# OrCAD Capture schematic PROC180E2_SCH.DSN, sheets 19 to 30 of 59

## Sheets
19 52. CURRENT MONITORING - 2: size C; title: CURRENT MONITORING DEVICES - 2
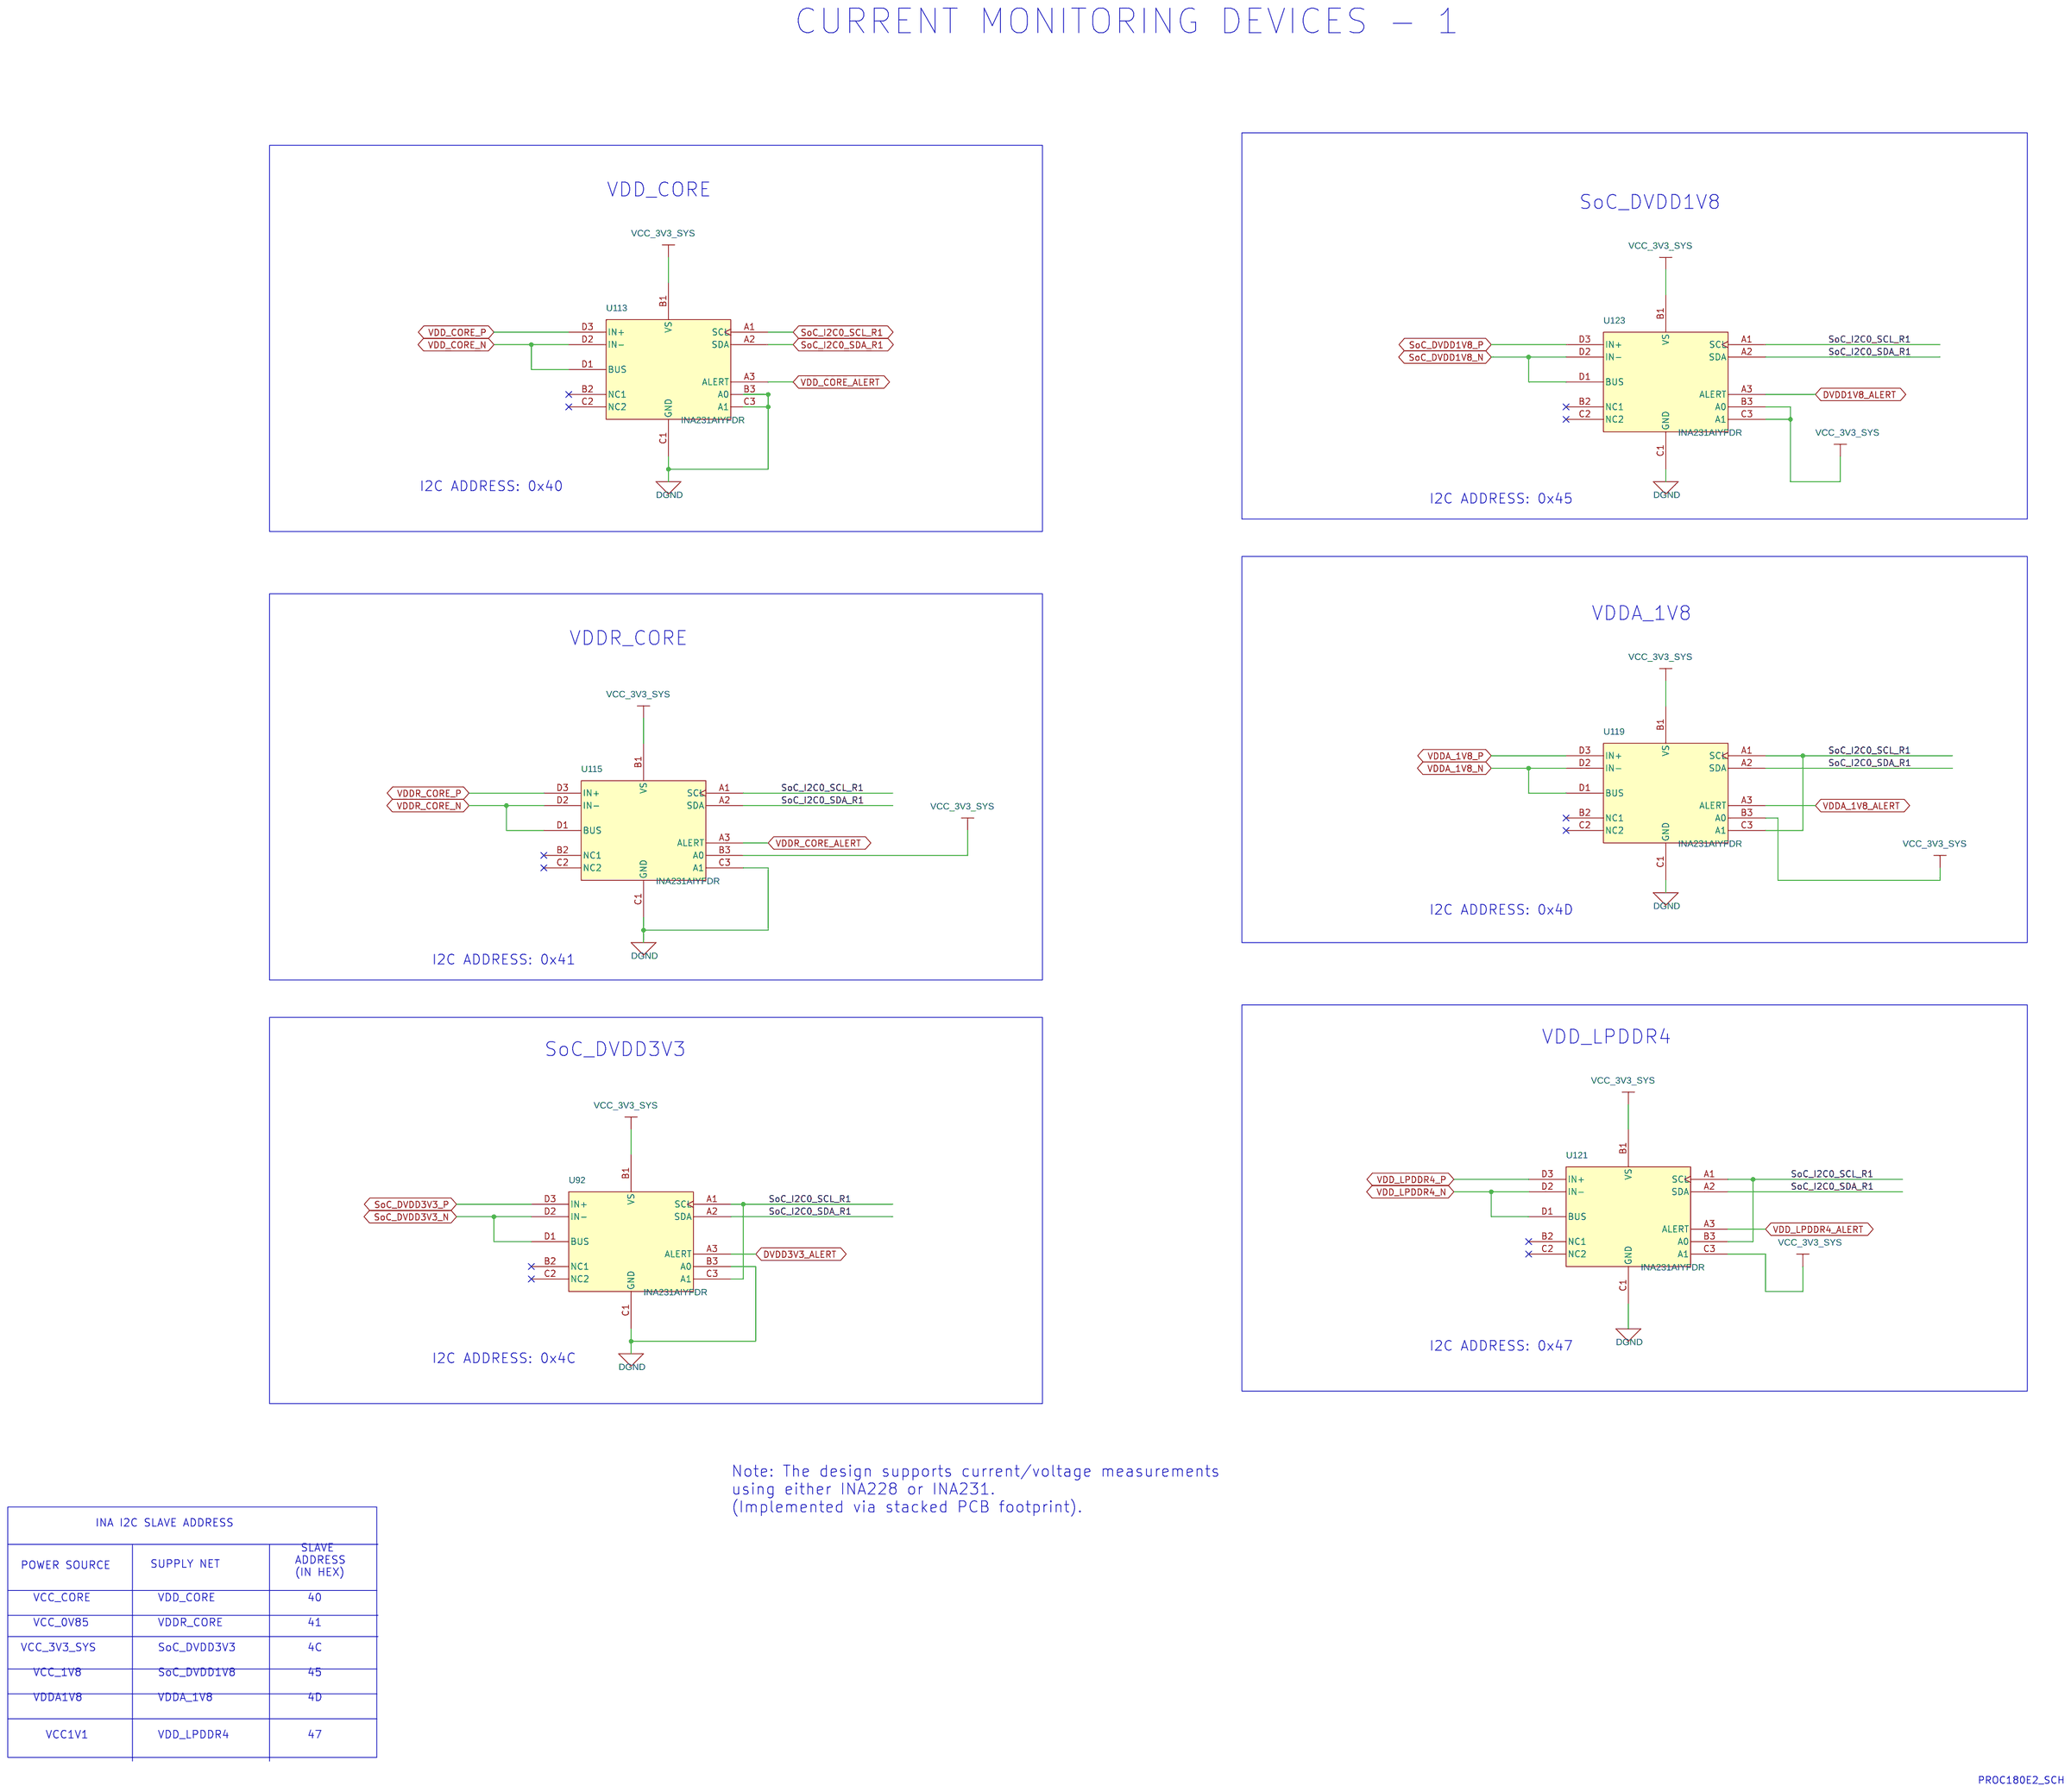
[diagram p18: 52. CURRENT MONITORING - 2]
20 37. CPLD 2: size C; title: CPLD 2
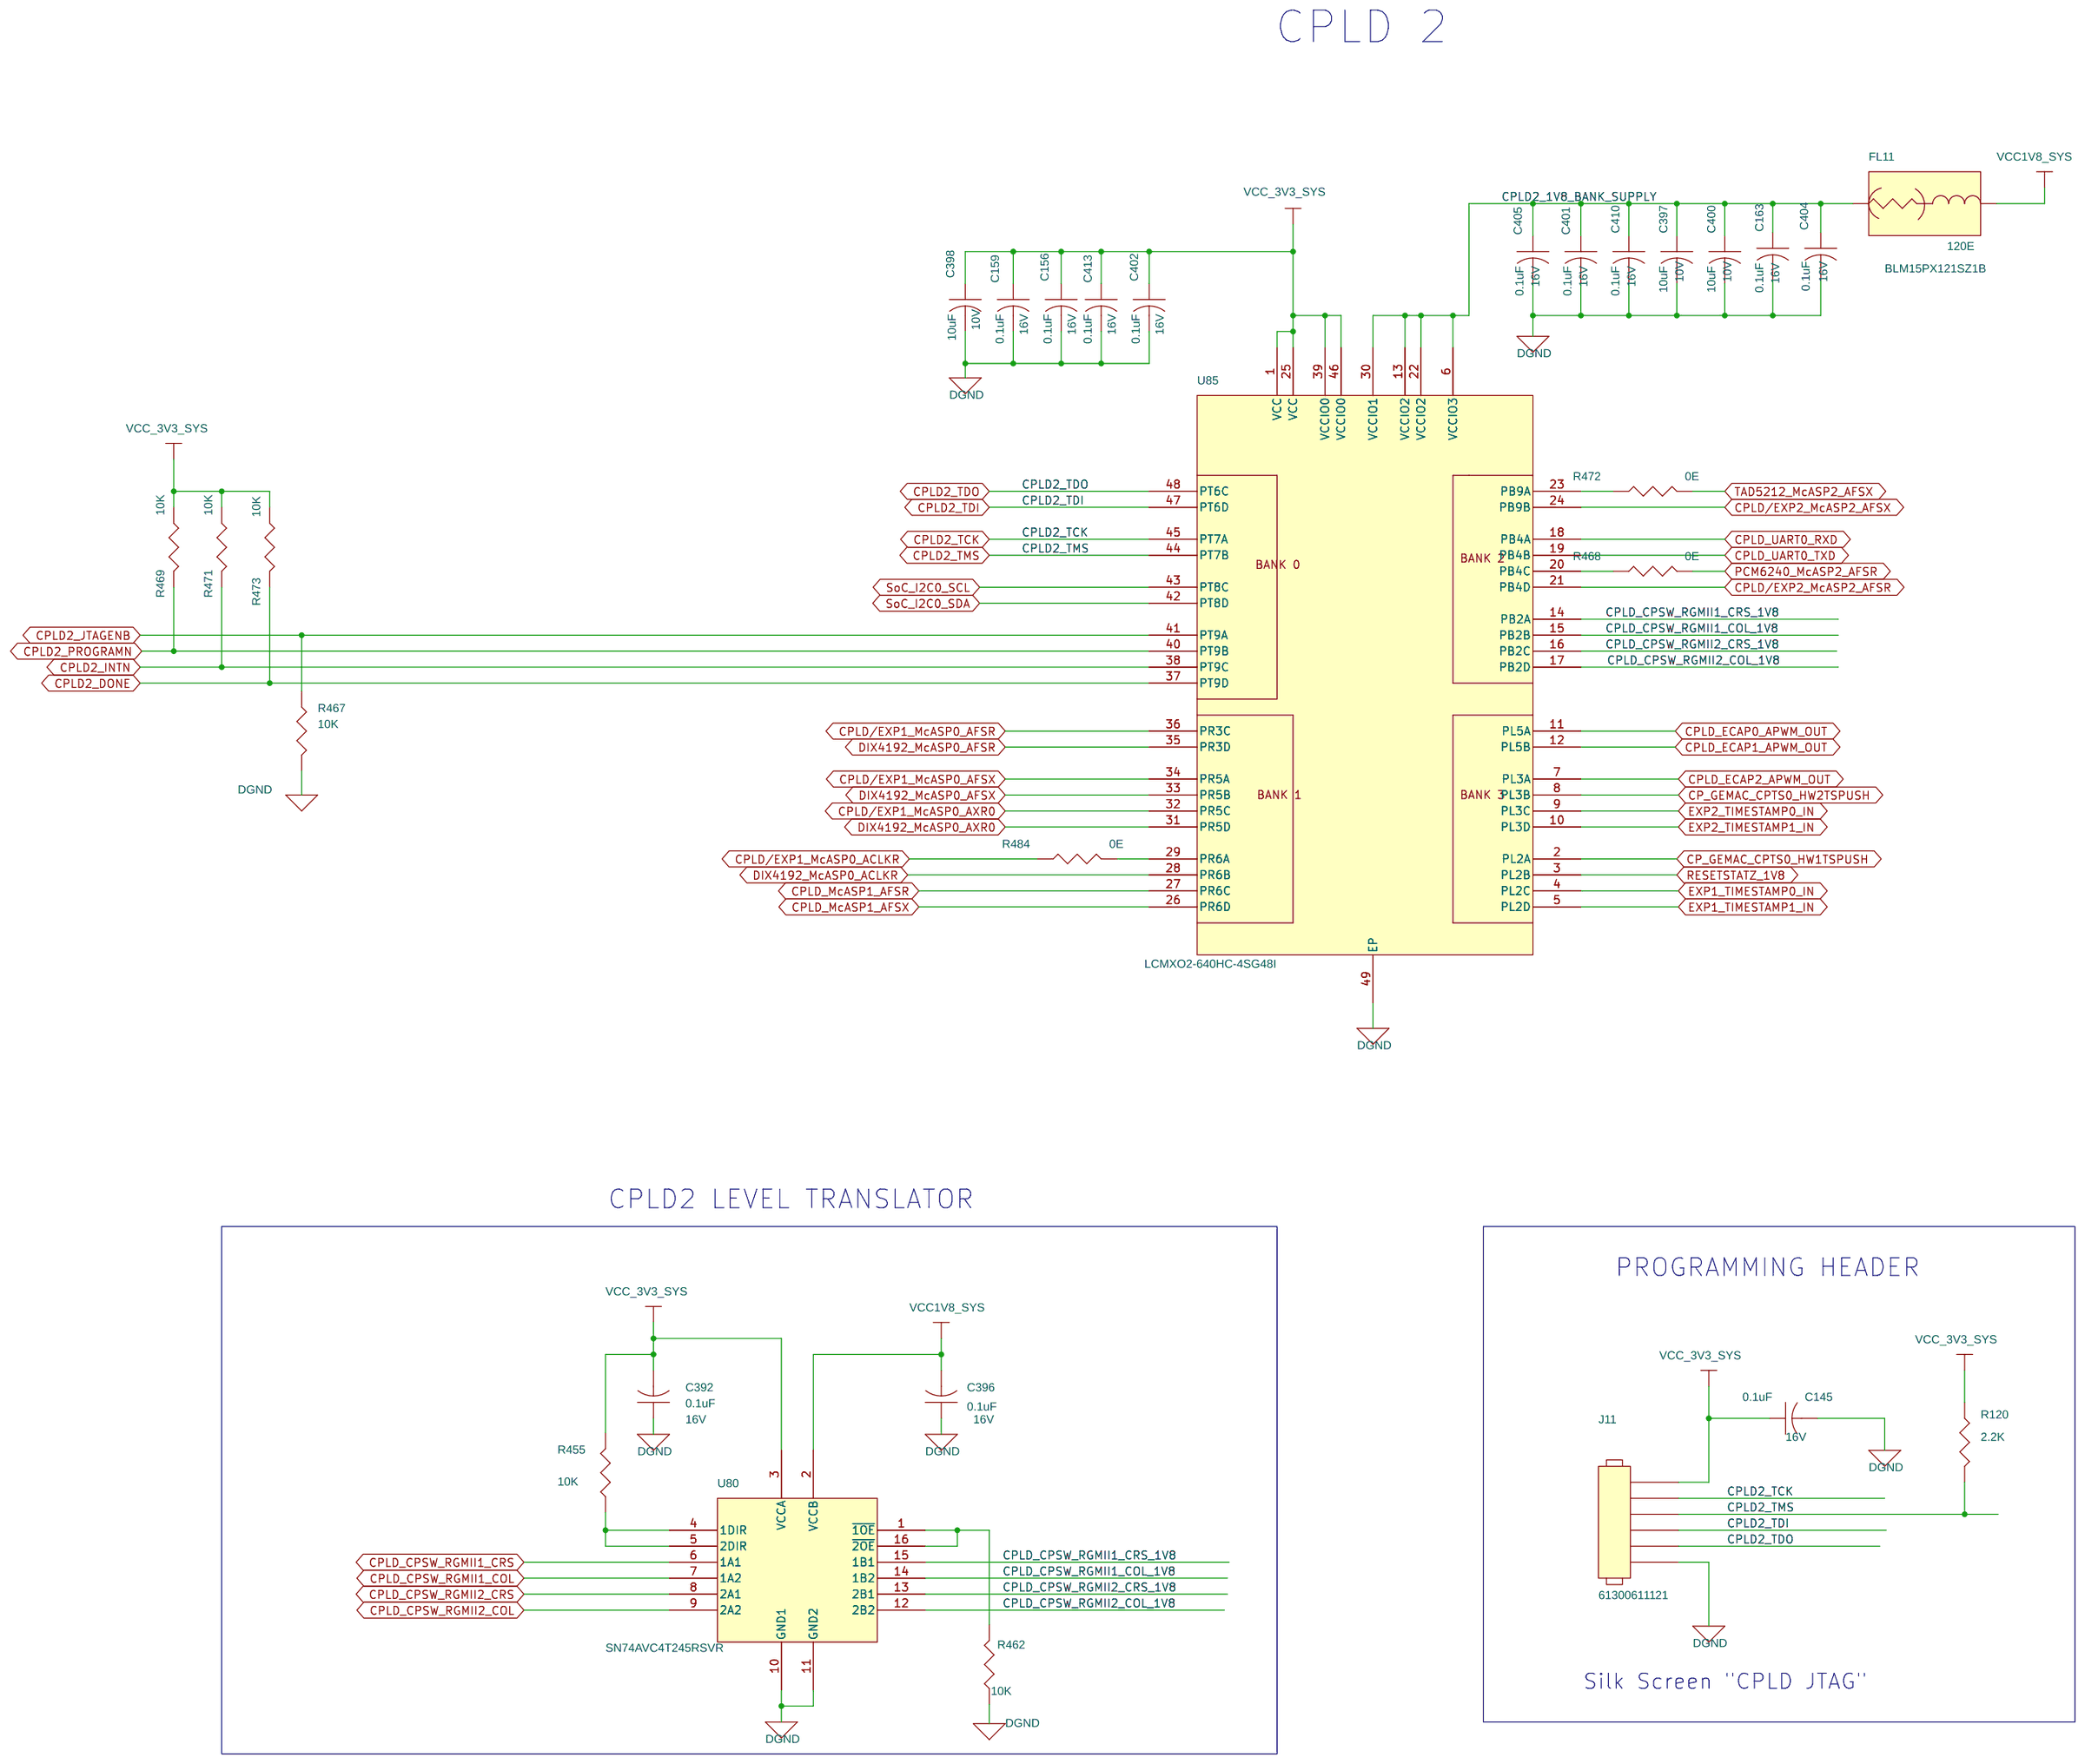
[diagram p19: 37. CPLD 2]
21 41. AUDIO LINEOUT - 2: size C; title: AUDIO - STEREO LINEOUT - 2
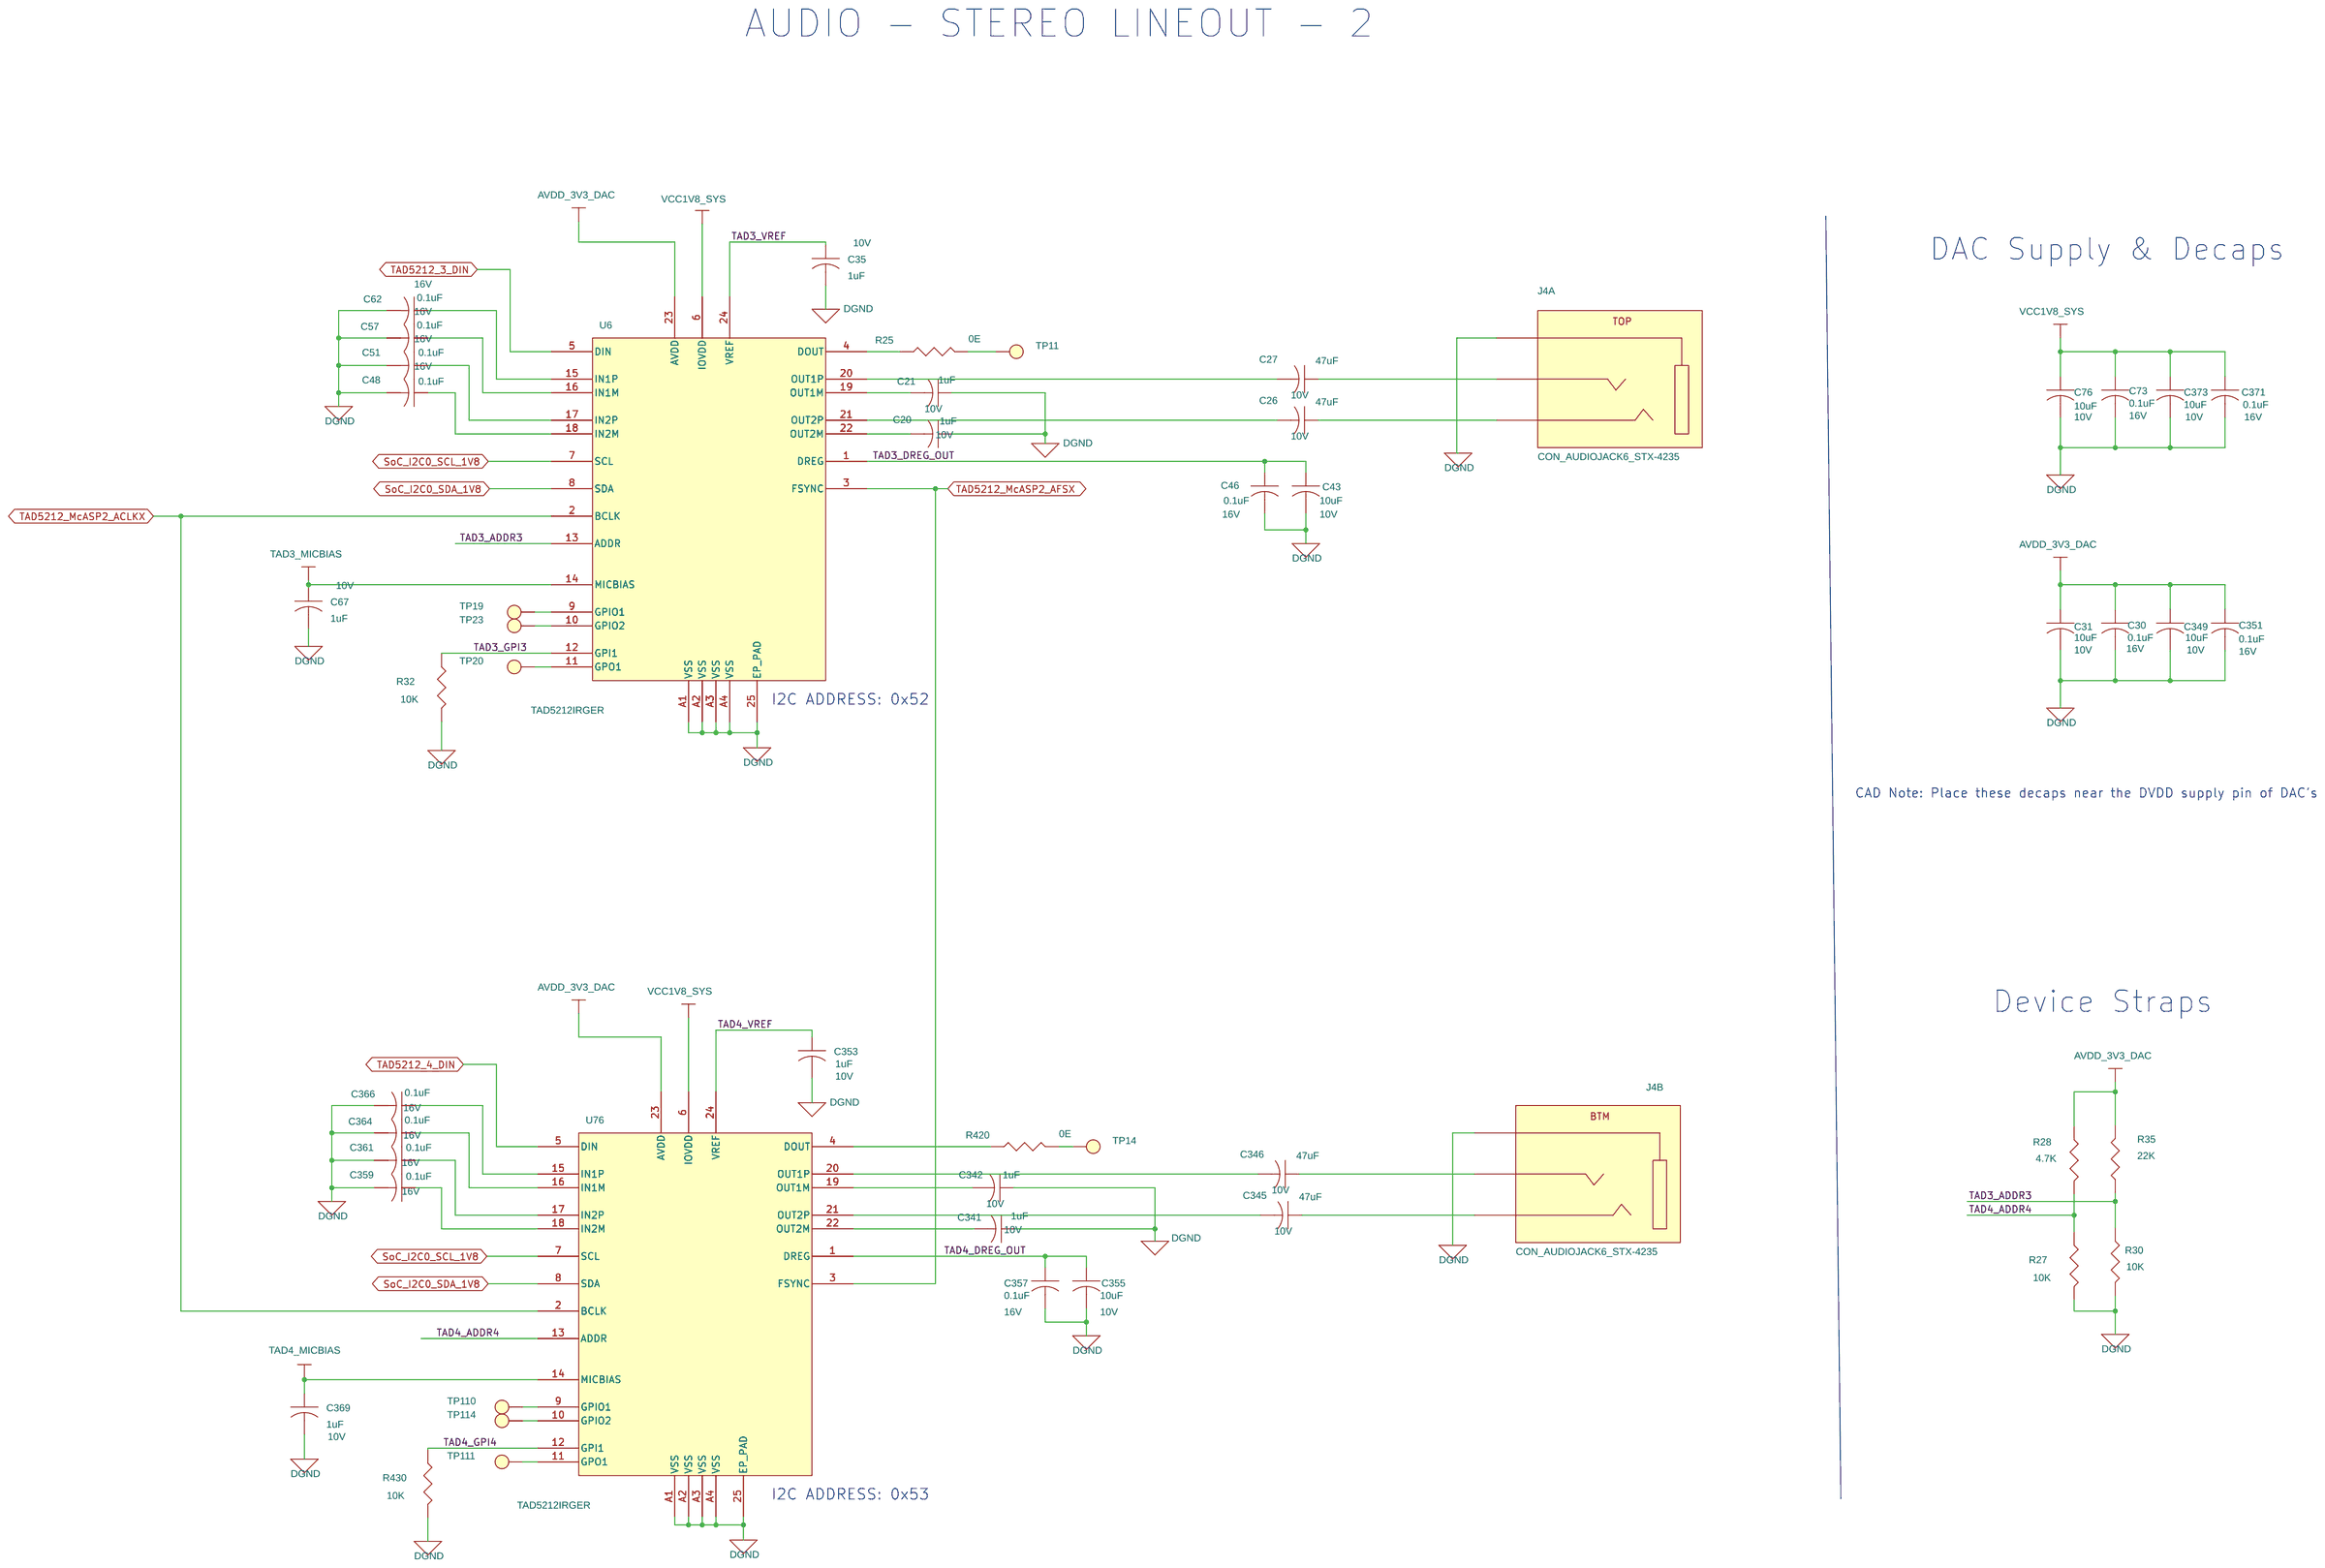
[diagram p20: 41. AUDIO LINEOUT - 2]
22 36. CPLD 1: size C; title: CPLD 1
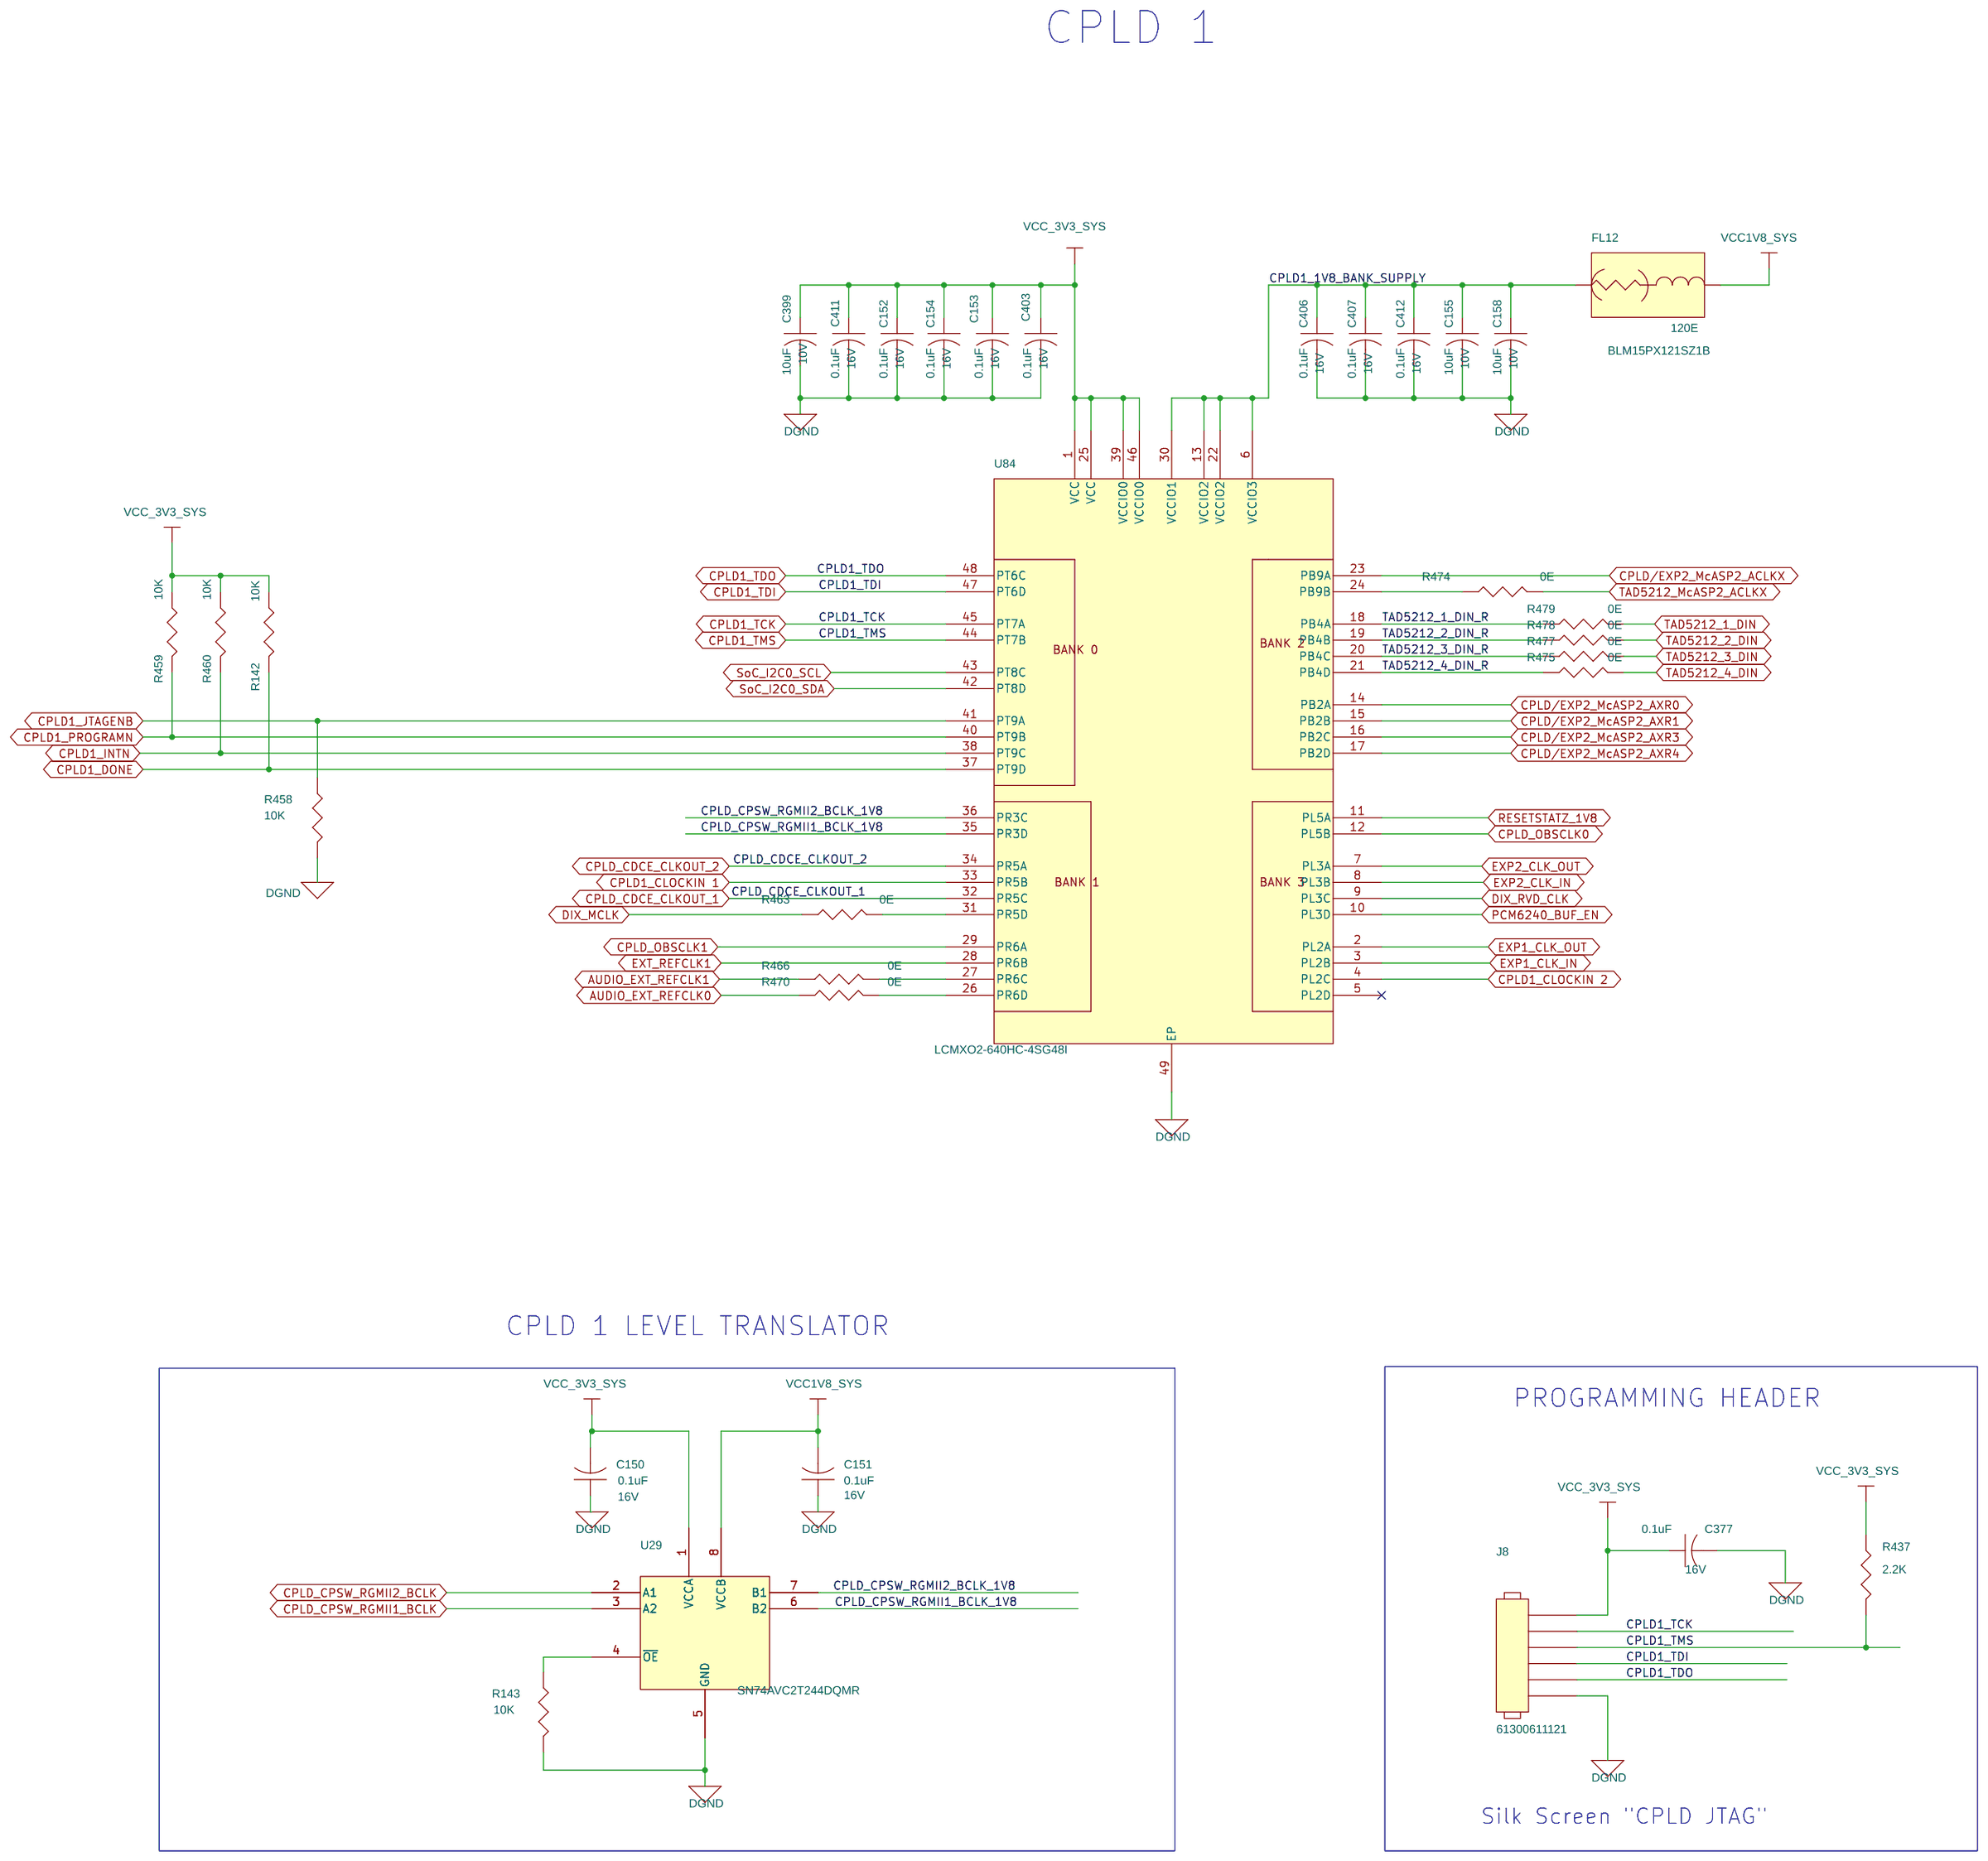
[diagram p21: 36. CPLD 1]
23 01. TABLE OF CONTENTS: title: TABLE OF CONTENTS
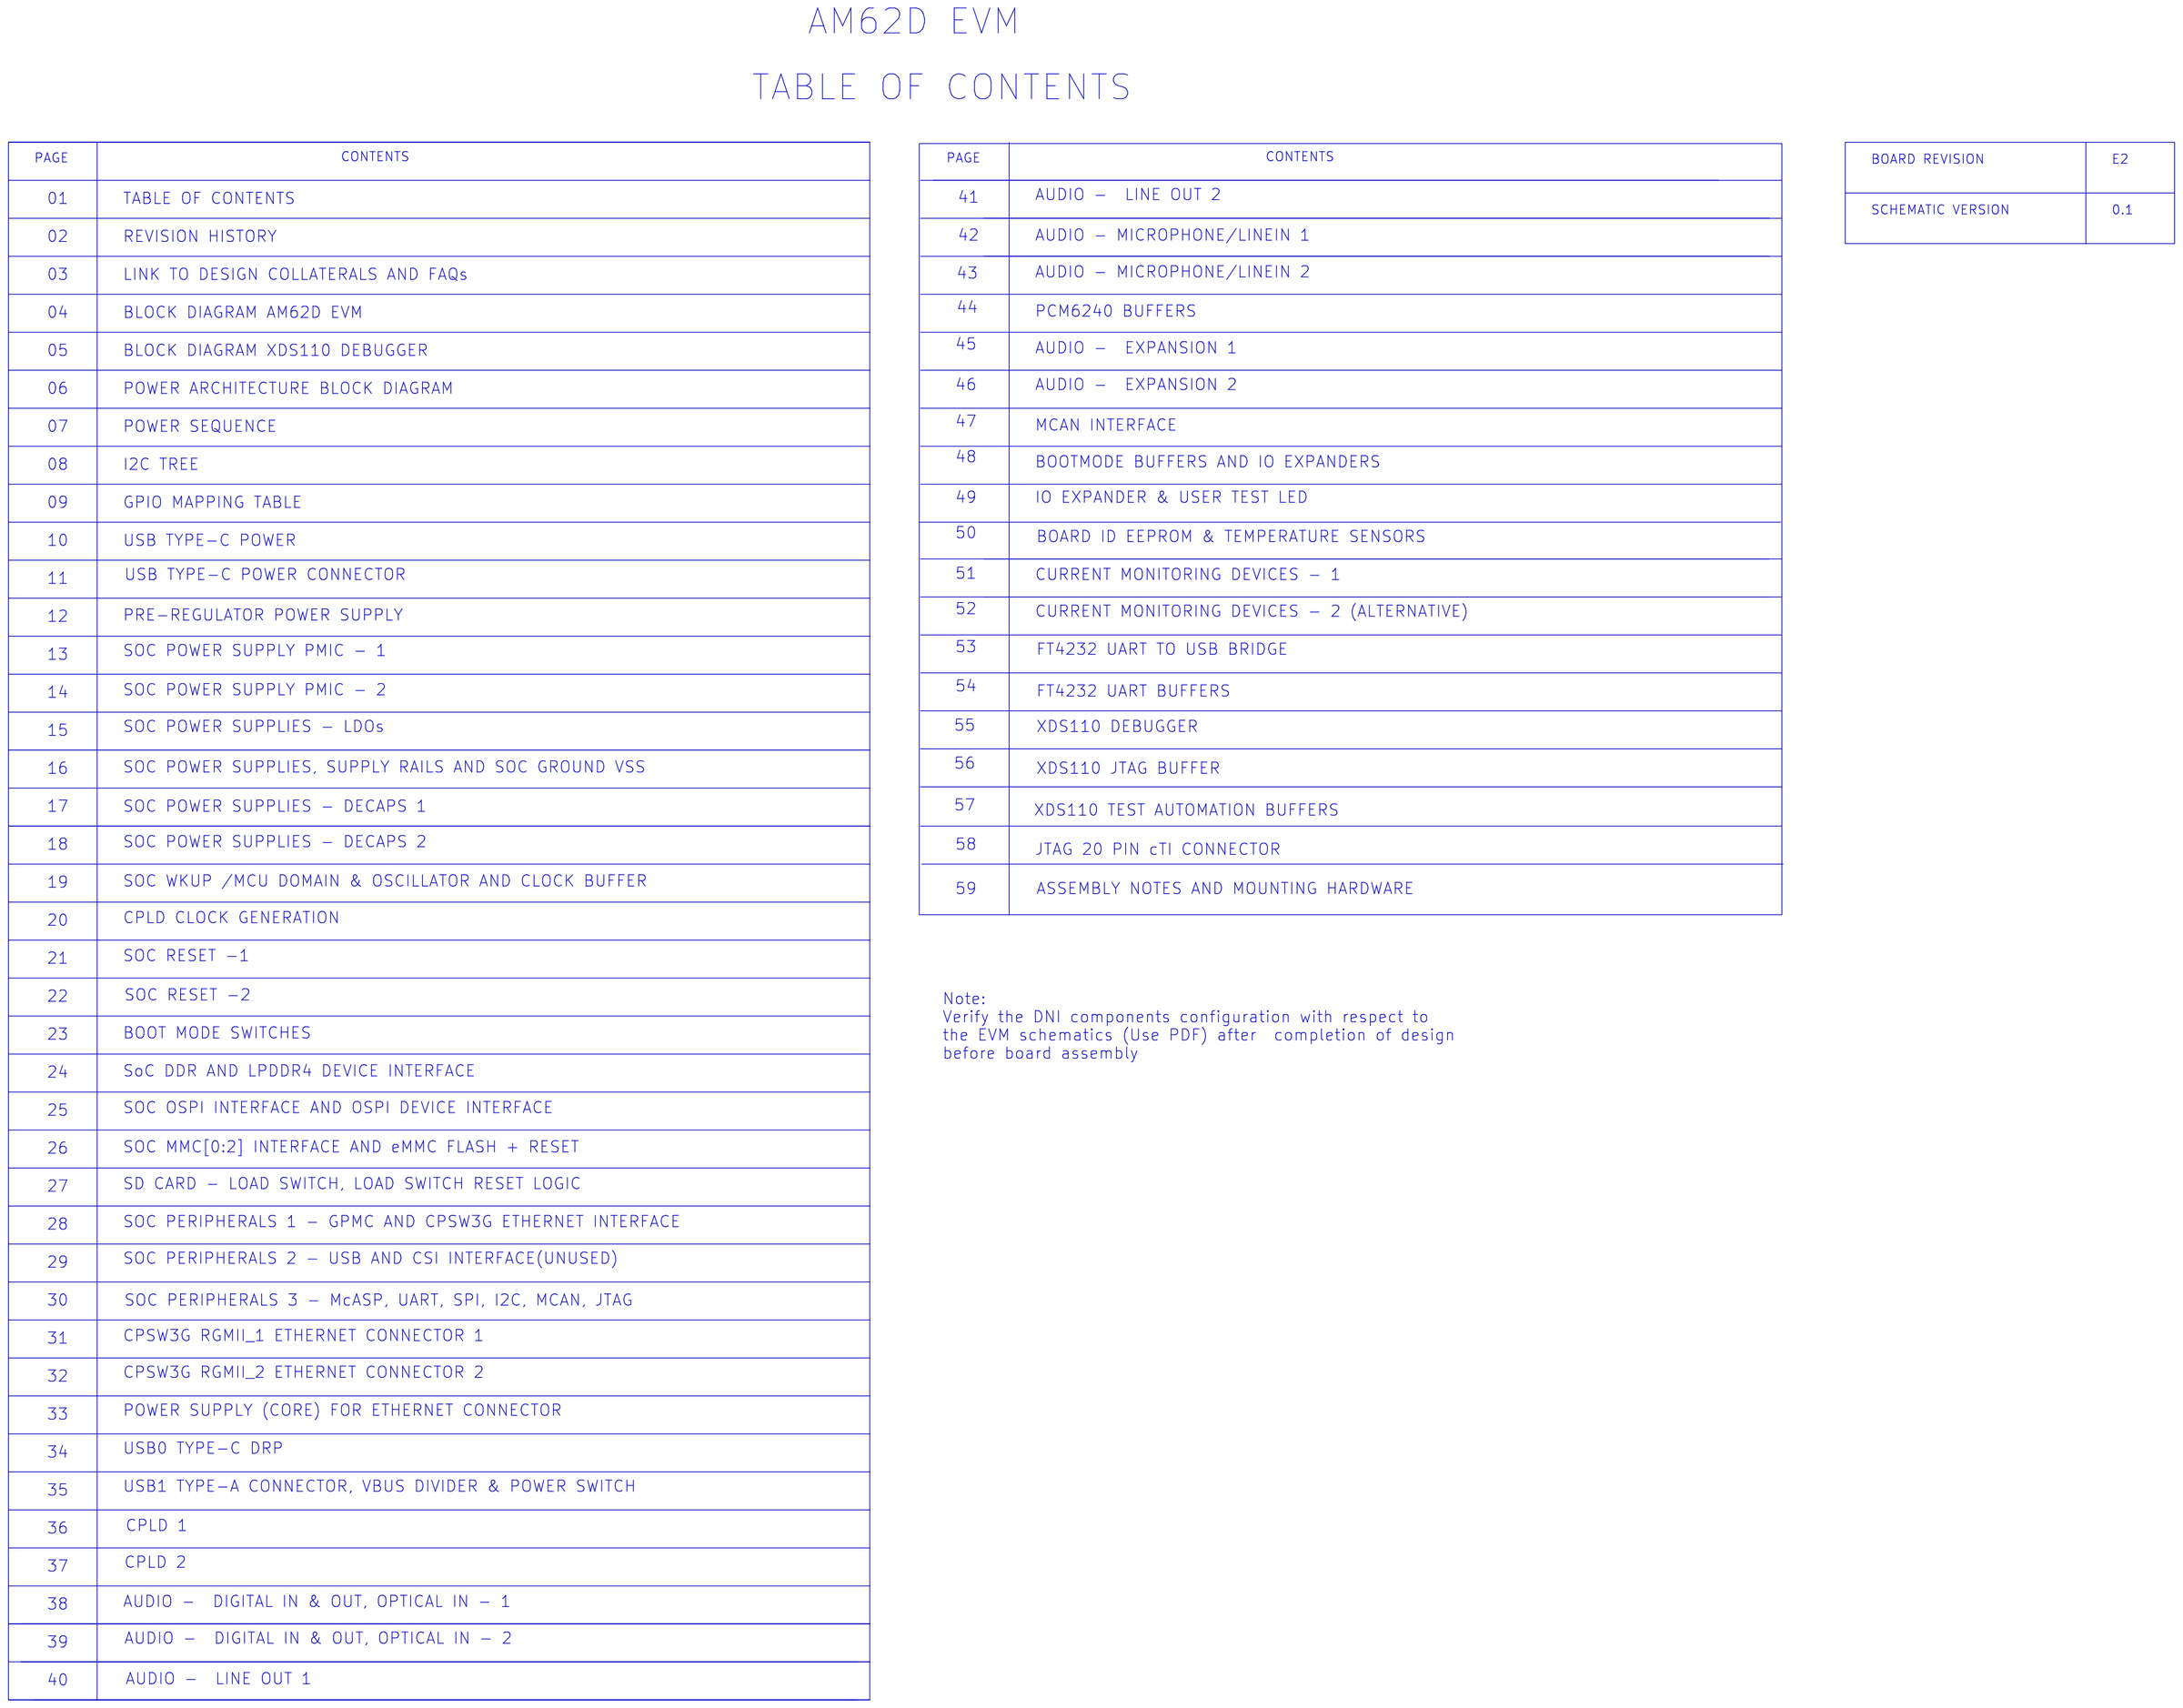
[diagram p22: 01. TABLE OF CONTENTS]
24 02. REVISION HISTORY: title: REVISION HISTORY
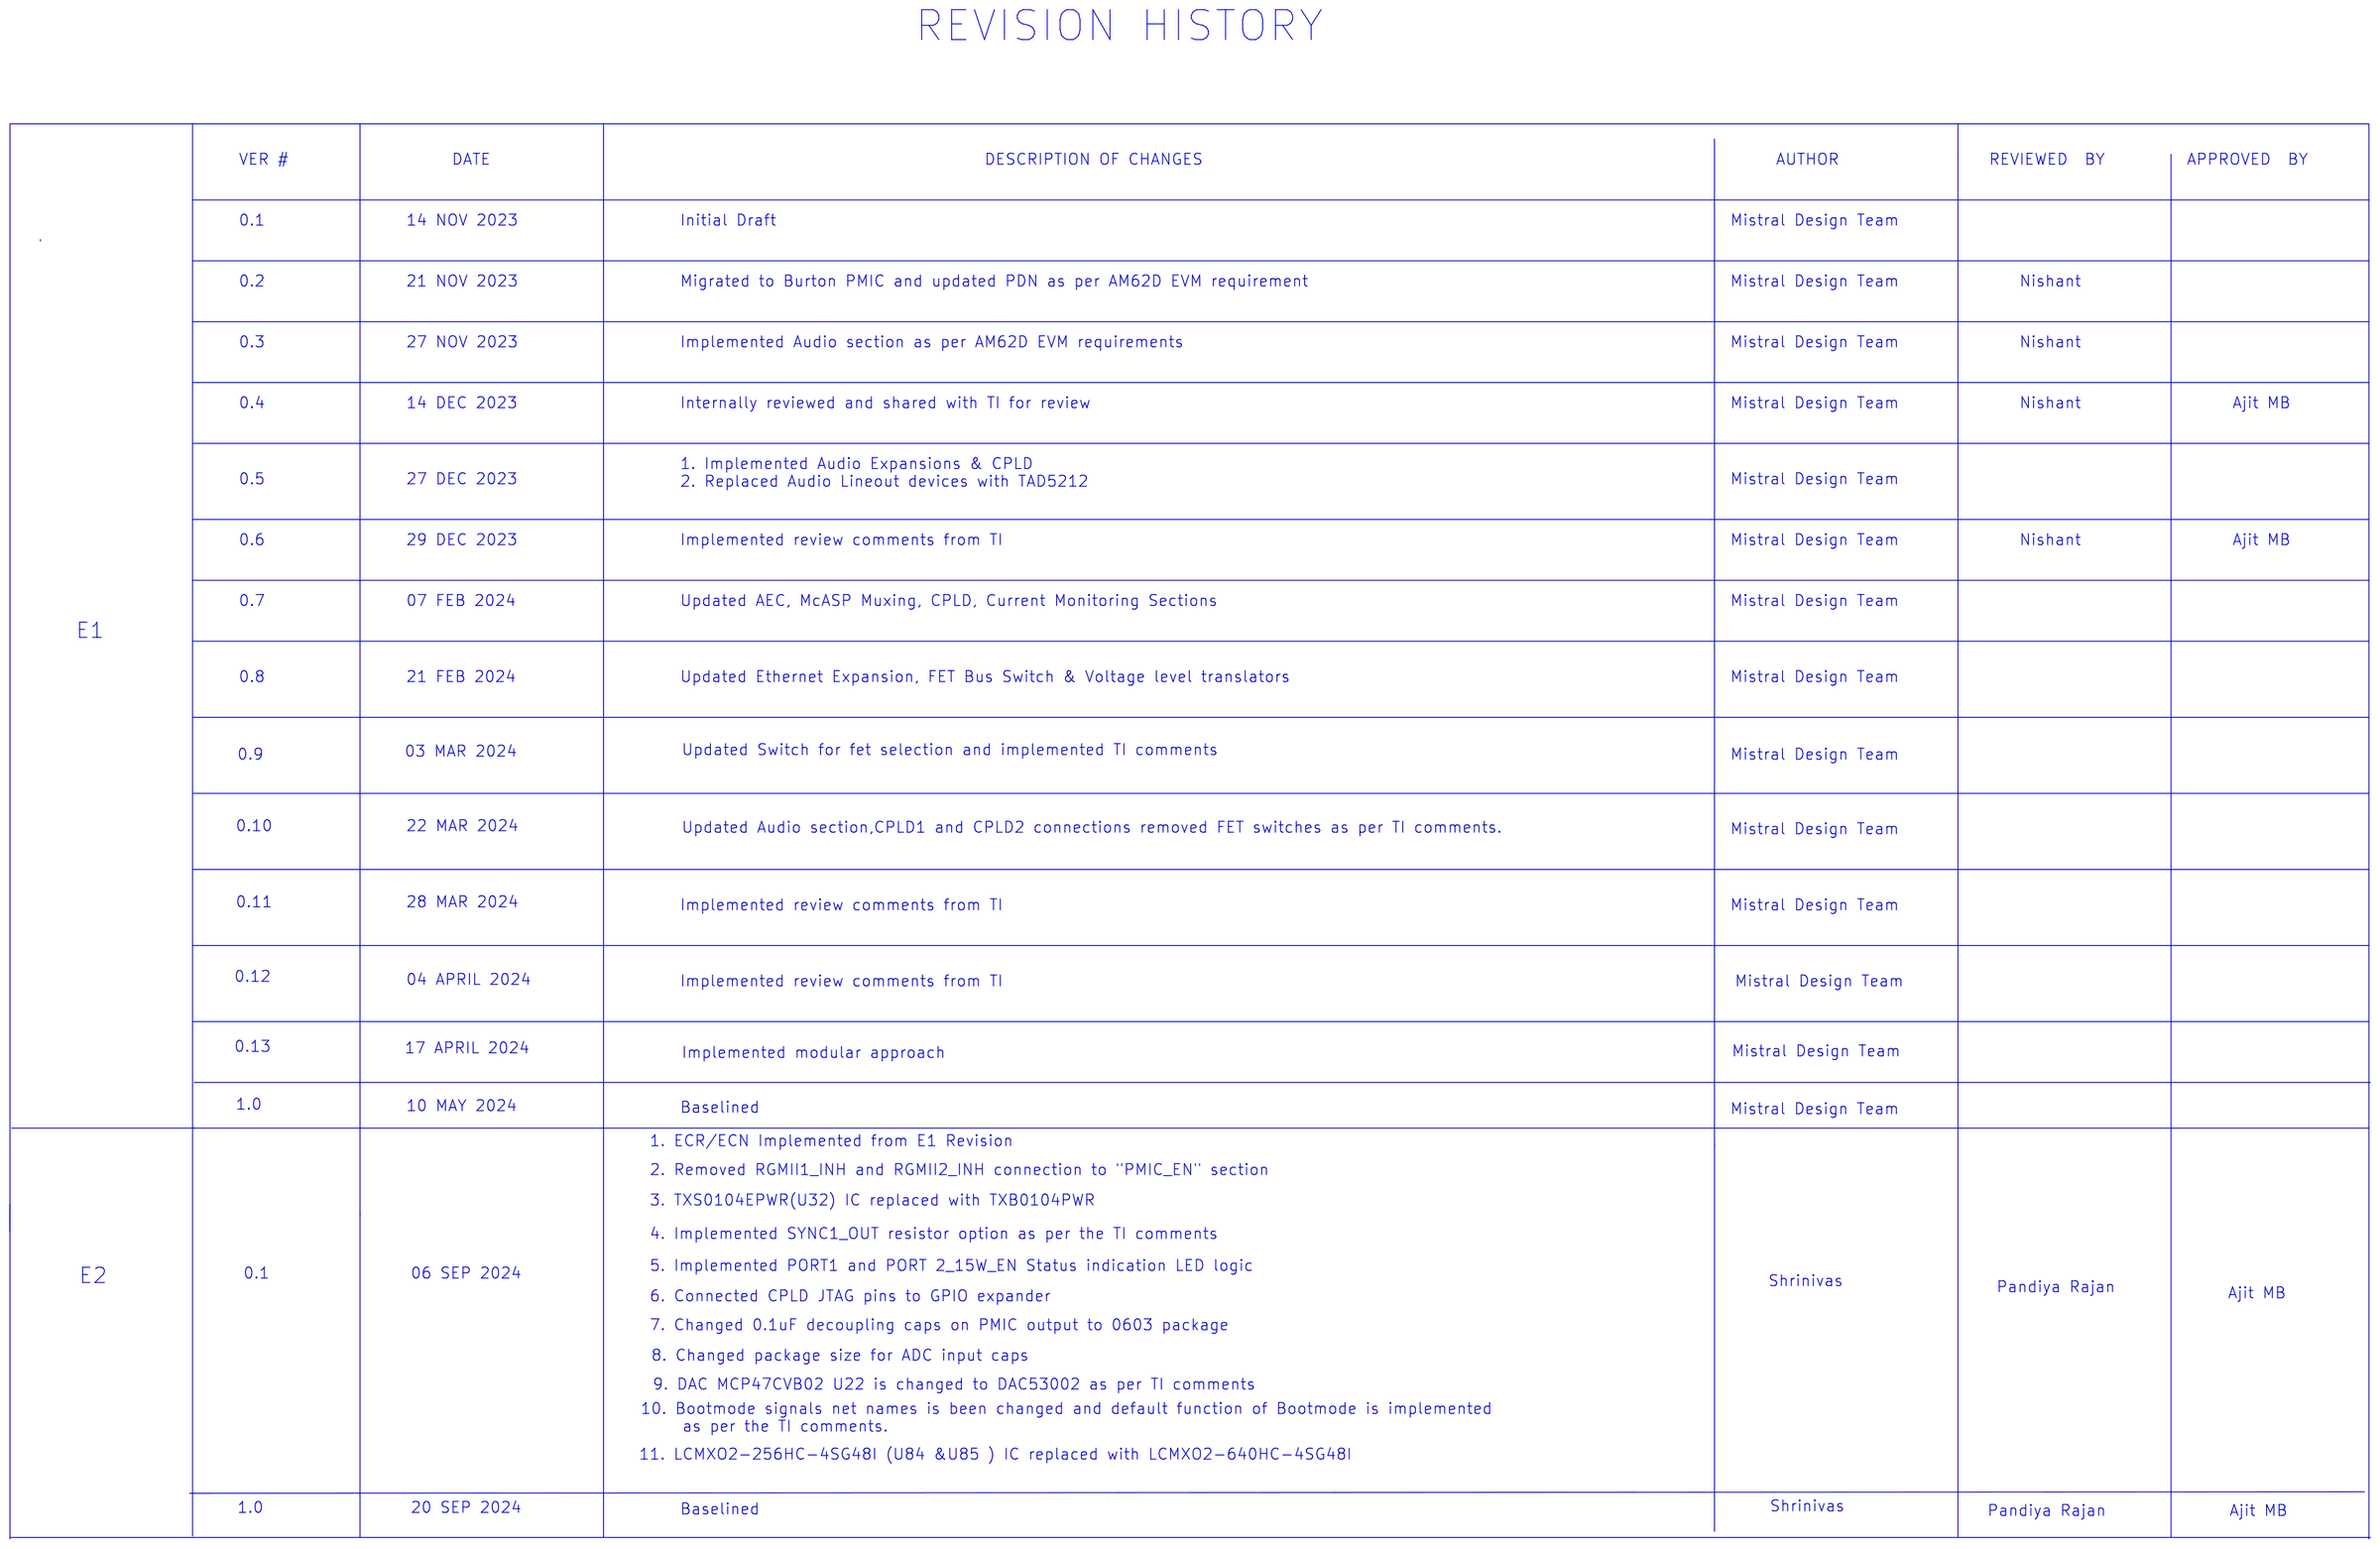
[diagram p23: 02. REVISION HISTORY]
25 04. BLOCK DGM AM62D-EVM: title: BLOCK DIAGRAM AM62D_ SKEVM
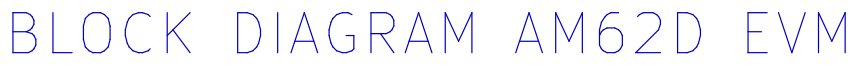
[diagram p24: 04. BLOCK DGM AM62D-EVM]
26 05. BLOCK DIAGRAM_XDS110: title: BLOCK DIAGRAM_XDS110
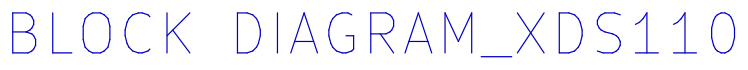
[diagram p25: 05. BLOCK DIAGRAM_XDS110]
27 06. POWER BLOCK DGM: title: POWER ARCHITECTURE BLOCK DIAGRAM
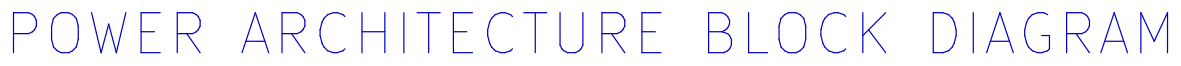
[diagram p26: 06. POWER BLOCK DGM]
28 07. POWER SEQUENCE: title: POWER SEQUENCE
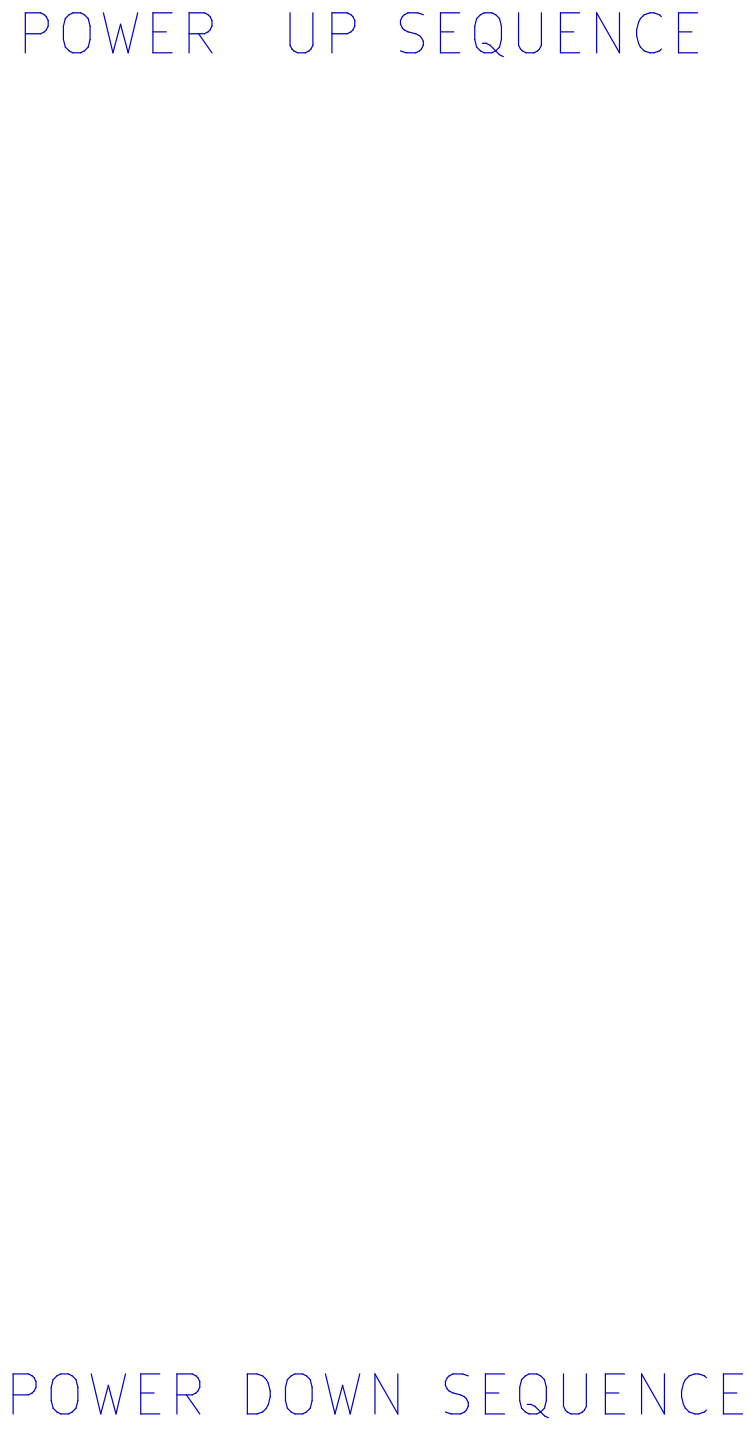
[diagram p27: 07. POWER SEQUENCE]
29 08. I2C TREE: title: I2C TREE
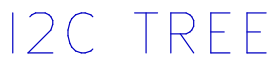
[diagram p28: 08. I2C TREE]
30 09. GPIO MAPPING TABLE: title: GPIO MAPPING TABLE
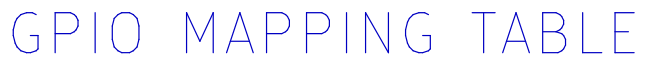
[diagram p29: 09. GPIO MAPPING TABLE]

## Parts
sheet 36. CPLD 1
C150  0.1uF  [CAP0201_0-5]
C151  0.1uF  [CAP0201_0-5]
C152  0.1uF  [CAP0201_0-5]
C153  0.1uF  [CAP0201_0-5]
C154  0.1uF  [CAP0201_0-5]
C155  10uF  [CAP0402_0-75]
C158  10uF  [CAP0402_0-75]
C377  0.1uF  [CAP0201_0-5]
C399  10uF  [CAP0402_0-75]
C403  0.1uF  [CAP0201_0-5]
C406  0.1uF  [CAP0201_0-5]
C407  0.1uF  [CAP0201_0-5]
C411  0.1uF  [CAP0201_0-5]
C412  0.1uF  [CAP0201_0-5]
FL12  120E  [EMIFIL_BLM15A_0402_0-6]
J8  HDR_1X6  [HDR_1X6_61300611121_S_T_8-6]
R142  10K  [RES0201_0-5]
R143  10K  [RES0201_0-5]
R437  2.2K  [RES0201_0-5]
R458  10K  [RES0201_0-5]
R459  10K  [RES0201_0-5]
R460  10K  [RES0201_0-5]
R463  0E  [RES0201_0-5]
R466  0E  [RES0402_0-5]
R470  0E  [RES0402_0-5]
R474  0E  [RES0201_0-5]
R475  0E  [RES0201_0-5]
R477  0E  [RES0201_0-5]
R478  0E  [RES0201_0-5]
R479  0E  [RES0201_0-5]
U29  SN74AVC2T244DQMR  [X2SON8_15-74_70X50]
U84  LCMXO2-640HC-4SG48I  [QFN48_19-68_280X280_1_EP5-4]
sheet 37. CPLD 2
C145  0.1uF  [CAP0201_0-5]
C156  0.1uF  [CAP0201_0-5]
C159  0.1uF  [CAP0201_0-5]
C163  0.1uF  [CAP0201_0-5]
C392  0.1uF  [CAP0201_0-5]
C396  0.1uF  [CAP0201_0-5]
C397  10uF  [CAP0402_0-75]
C398  10uF  [CAP0402_0-75]
C400  10uF  [CAP0402_0-75]
C401  0.1uF  [CAP0201_0-5]
C402  0.1uF  [CAP0201_0-5]
C404  0.1uF  [CAP0201_0-5]
C405  0.1uF  [CAP0201_0-5]
C410  0.1uF  [CAP0201_0-5]
C413  0.1uF  [CAP0201_0-5]
FL11  120E  [EMIFIL_BLM15A_0402_0-6]
J11  HDR_1X6  [HDR_1X6_61300611121_S_T_8-6]
R120  2.2K  [RES0201_0-5]
R455  10K  [RES0201_0-5]
R462  10K  [RES0201_0-5]
R467  10K  [RES0201_0-5]
R468  0E  [RES0201_0-5]
R469  10K  [RES0201_0-5]
R471  10K  [RES0201_0-5]
R472  0E  [RES0201_0-5]
R473  10K  [RES0201_0-5]
R484  0E  [RES0201_0-5]
U80  SN74AVC4T245RSVR  [UQFN16_TMUX1574_70X100_0-6]
U85  LCMXO2-640HC-4SG48I  [QFN48_19-68_280X280_1_EP5-4]
sheet 41. AUDIO LINEOUT - 2
C20  1uF  [CAP0201_0-5]
C21  1uF  [CAP0201_0-5]
C26  47uF  [CAP0805_1-5]
C27  47uF  [CAP0805_1-5]
C30  0.1uF  [CAP0201_0-5]
C31  10uF  [CAP0402_0-75]
C35  1uF  [CAP0201_0-5]
C43  10uF  [CAP0402_0-75]
C46  0.1uF  [CAP0201_0-5]
C48  0.1uF  [CAP0201_0-5]
C51  0.1uF  [CAP0201_0-5]
C57  0.1uF  [CAP0201_0-5]
C62  0.1uF  [CAP0201_0-5]
C67  1uF  [CAP0201_0-5]
C73  0.1uF  [CAP0201_0-5]
C76  10uF  [CAP0402_0-75]
C341  1uF  [CAP0201_0-5]
C342  1uF  [CAP0201_0-5]
C345  47uF  [CAP0805_1-5]
C346  47uF  [CAP0805_1-5]
C349  10uF  [CAP0402_0-75]
C351  0.1uF  [CAP0201_0-5]
C353  1uF  [CAP0201_0-5]
C355  10uF  [CAP0402_0-75]
C357  0.1uF  [CAP0201_0-5]
C359  0.1uF  [CAP0201_0-5]
C361  0.1uF  [CAP0201_0-5]
C364  0.1uF  [CAP0201_0-5]
C366  0.1uF  [CAP0201_0-5]
C369  1uF  [CAP0201_0-5]
C371  0.1uF  [CAP0201_0-5]
C373  10uF  [CAP0402_0-75]
J4  CON_AUDIOJACK6_STX-4235  [CON_AV6_STX-4235-3-3_S_R_T_26]  (sections A,B)
R25  0E  [RES0201_0-5]
R27  10K  [RES0201_0-5]
R28  4.7K  [RES0201_0-5]
R30  10K  [RES0201_0-5]
R32  10K  [RES0201_0-5]
R35  22K  [RES0402_0-5]
R420  0E  [RES0201_0-5]
R430  10K  [RES0201_0-5]
TP11  TP30_SMD  [TP30_SMD]
TP14  TP30_SMD  [TP30_SMD]
TP19  TP30_SMD  [TP30_SMD]
TP20  TP30_SMD  [TP30_SMD]
TP23  TP30_SMD  [TP30_SMD]
TP110  TP30_SMD  [TP30_SMD]
TP111  TP30_SMD  [TP30_SMD]
TP114  TP30_SMD  [TP30_SMD]
U6  TAD5212IRGER  [QFN24_TAD5212IRGER_160X160_1]
U76  TAD5212IRGER  [QFN24_TAD5212IRGER_160X160_1]
sheet 52. CURRENT MONITORING - 2
U92  INA231AIYFDR  [DSBGA12_15-74_60X70_0-4]
U113  INA231AIYFDR  [DSBGA12_15-74_60X70_0-4]
U115  INA231AIYFDR  [DSBGA12_15-74_60X70_0-4]
U119  INA231AIYFDR  [DSBGA12_15-74_60X70_0-4]
U121  INA231AIYFDR  [DSBGA12_15-74_60X70_0-4]
U123  INA231AIYFDR  [DSBGA12_15-74_60X70_0-4]

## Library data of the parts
C150 C151 C392 C396 = CAP: CAP CERAMIC 0.1uF 16V 10% X7S AUTO 0201; Alt_Mfr_name: YAGEO AMERICA; Alt_Mfr_part_number: CC0402KRX5R8BB104; Chkd/date: MANIRAJA/110321; Crtd /date: ALVY/110321; Custom_Duty: 15%; Customs_HS_Code: 85322990; Distributor_name: DIGIKEY; Distributor_part_number: 490-GRT033C71C104KE01DTR-ND; Footprint Path: Y:\MIS_DATABASE\Library\ALTIUM_TOOL\PCB_FOOTPRINTS\Altium_Footprint_Lib.PcbLib; Height: 0.33MM; Library Path: Y:\MIS_DATABASE\Library\ALTIUM_TOOL\SCHEMATICS_PARTS\MS_DISCRETE_Library.schlib; Mfr_name: MURATA; Mfr_part_number: GRT033C71C104KE01D; Mistral Part No: 120021030007-R; Package: 0201; Part_type: CAPACITORS\CERAMIC; Project: J7ES_SK_BRD; RoHS: RoHS; Temperature: -55°C+125°C; Tolerance: 10%; Voltage: 16V; Wattage: NA; Weight: 330mg; Datasheet: Y:\MIS_DATABASE\DATASHEETS\CAPACITORS\GRT033C71C104KE01.PDF
C30 C46 C48 C51 C57 C62 C73 C145 C152-C154 C156 C159 C163 C351 C357 C359 C361 C364 C366 C371 C377 C401-C407 C410-C413 = CAP: CAP CERAMIC 0.1uF 16V 10% X7S AUTO 0201; Chkd/date: MANIRAJA/110321; Crtd /date: ALVY/110321; Custom_Duty: 15%; Customs_HS_Code: 85322990; Distributor_name: DIGIKEY; Distributor_part_number: 490-GRT033C71C104KE01DTR-ND; Footprint Path: Y:\MIS_DATABASE\Library\ALTIUM_TOOL\PCB_FOOTPRINTS\Altium_Footprint_Lib.PcbLib; Height: 0.33MM; Library Path: Y:\MIS_DATABASE\Library\ALTIUM_TOOL\SCHEMATICS_PARTS\MS_DISCRETE_Library.schlib; Mfr_name: MURATA; Mfr_part_number: GRT033C71C104KE01D; Mistral Part No: 120021030007-R; Package: 0201; Part_type: CAPACITORS\CERAMIC; Project: J7ES_SK_BRD; RoHS: RoHS; Temperature: -55°C+125°C; Tolerance: 10%; Voltage: 16V; Wattage: NA; Weight: 330mg; Datasheet: Y:\MIS_DATABASE\DATASHEETS\CAPACITORS\GRT033C71C104KE01.PDF
C31 C43 C76 C155 C158 C349 C355 C373 C397-C400 = CAP: CAP CERAMIC 10uF 10V 20% X5R 0402; Chkd/date: PRADEEP/130623; Crtd /date: PRADEEP/130623; Custom_Duty: 15%; Customs_HS_Code: 85322990; Distributor_name: NA; Distributor_part_number: NA; Footprint Path: Y:\MIS_DATABASE\Library\ALTIUM_TOOL\PCB_FOOTPRINTS\Altium_Footprint_Lib.PcbLib; Height: 0.55MM; Library Path: Y:\MIS_DATABASE\Library\ALTIUM_TOOL\SCHEMATICS_PARTS\MS_DISCRETE_Library.schlib; Mfr_name: MURATA; Mfr_part_number: GRM155R61A106ME18; Mistral Part No: 120022060018-R; Package: 0402; Part_type: CAPACITORS\CERAMIC; Project: AM62P_SK; RoHS: RoHS; Temperature: -55°C+85°C; Tolerance: 20%; Voltage: 10V; Wattage: NA; Weight: 6mg; Datasheet: Y:\MIS_DATABASE\DATASHEETS\CAPACITORS\MURATA-GXX-SER_NOV17.PDF
FL11 FL12 = EMIFILTER_IND: IND FERRITE BEAD CHIP 120E 2A 0402; Chkd/date: MANIRAJA/311221; Crtd /date: ALVY/301221; Custom_Duty: 24%; Customs_HS_Code: 85437099; Distributor_name: NA; Distributor_part_number: NA; Footprint Path: Y:\MIS_DATABASE\Library\ALTIUM_TOOL\PCB_FOOTPRINTS\Altium_Footprint_Lib.PcbLib; Height: 0.55MM; Library Path: Y:\MIS_DATABASE\Library\ALTIUM_TOOL\SCHEMATICS_PARTS\MS_FILTER_Library.schlib; Mfr_name: MURATA; Mfr_part_number: BLM15PX121SZ1B; Mistral Part No: 130021120017-R; Package: 0402; Part_type: INDUCTOR; Project: AM62Q_SKEVM_BRD; RoHS: RoHS; Temperature: -55°C+125°C; Tolerance: 25%; Voltage: NA; Wattage: NA; Weight: 1mg; Datasheet: Y:\MIS_DATABASE\DATASHEETS\DISCRETES\INDUCTORS\BLM-SER.PDF
J8 J11 = HEADER_6X1: CON HDR 1X6 2.54MM PITCH ST TH; Chkd/date: MANIRAJA/161219; Crtd /date: MANIRAJA/161219; Custom_Duty: 24%; Customs_HS_Code: 85369090; Distributor_name: DIGIKEY; Distributor_part_number: 732-5319-ND; Footprint Path: Y:\MIS_DATABASE\Library\ALTIUM_TOOL\PCB_FOOTPRINTS\Altium_Footprint_Lib.PcbLib; Height: 8.54MM; Library Path: Y:\MIS_DATABASE\Library\ALTIUM_TOOL\SCHEMATICS_PARTS\MS_CONNECTOR_Library.schlib; Mfr_name: WURTH ELECTRONICS; Mfr_part_number: 61300611121; Mistral Part No: 150019120017-R; Package: THRU-HOLE; Part_type: CONNECTOR\HEADERS; Project: SD820_NANOSOM_TESTJIG; RoHS: RoHS; Temperature: -40°C+105°C; Tolerance: NA; Voltage: NA; Wattage: NA; Weight: 342.4mg; Datasheet: Y:\MIS_DATABASE\DATASHEETS\CONNECTORS\6130XXX.PDF
R27 R30 R32 R142 R143 R430 R455 R458-R460 R462 R467 R469 R471 R473 = RESISTOR: RES 10K 1/20W 5% 0201; Chkd/date: MANIRAJA/050517; Crtd /date: MANIRAJA/050517; Custom_Duty: 15%; Customs_HS_Code: 85332119; Distributor_name: DIGIKEY; Distributor_part_number: 311-10KNCT-ND; Footprint Path: Y:\MIS_DATABASE\Library\ALTIUM_TOOL\PCB_FOOTPRINTS\Altium_Footprint_Lib.PcbLib; Height: 0.26MM; Library Path: Y:\MIS_DATABASE\Library\ALTIUM_TOOL\SCHEMATICS_PARTS\MS_DISCRETE_Library.schlib; Mfr_name: YAGEO AMERICA; Mfr_part_number: RC0201JR-0710KL; Mistral Part No: 110010070051-R; Package: 0201; Part_type: RESISTORS\FIXED; Project: GOLDEN-I LITE; RoHS: RoHS; Temperature: -55°C+125°C; Tolerance: 5%; Voltage: NA; Wattage: 1/20W; Weight: 0.17mg; Datasheet: Y:\MIS_DATABASE\DATASHEETS\RESISTORS\RCXXXXL-SER_MAR18.PDF
R120 R437 = RESISTOR: RES 2.2K 1/20W 5% 0201; Chkd/date: MANIRAJA/050517; Crtd /date: MANIRAJA/050517; Custom_Duty: 15%; Customs_HS_Code: 85332119; Distributor_name: DIGIKEY; Distributor_part_number: 311-2.2KNCT-ND; Footprint Path: Y:\MIS_DATABASE\Library\ALTIUM_TOOL\PCB_FOOTPRINTS\Altium_Footprint_Lib.PcbLib; Height: 0.26MM; Library Path: Y:\MIS_DATABASE\Library\ALTIUM_TOOL\SCHEMATICS_PARTS\MS_DISCRETE_Library.schlib; Mfr_name: YAGEO AMERICA; Mfr_part_number: RC0201JR-072K2L; Mistral Part No: 110009030427-R; Package: 0201; Part_type: RESISTORS\FIXED; Project: GOLDEN-I LITE; RoHS: RoHS; Temperature: -55°C+125°C; Tolerance: 5%; Voltage: NA; Wattage: 1/20W; Weight: 0.17mg; Datasheet: Y:\MIS_DATABASE\DATASHEETS\RESISTORS\RCXXXXL-SER_MAR18.PDF
R463 R474 R475 R477-R479 = RESISTOR: RES 0E 1/20W 5% 0201; Chkd/date: NAVEED/301214; Crtd /date: MUDDU/120710; Custom_Duty: 15%; Customs_HS_Code: 85332119; Distributor_name: DIGIKEY; Distributor_part_number: 311-0.0NCT-ND; Footprint Path: Y:\MIS_DATABASE\Library\ALTIUM_TOOL\PCB_FOOTPRINTS\Altium_Footprint_Lib.PcbLib; Height: 0.26MM; Library Path: Y:\MIS_DATABASE\Library\ALTIUM_TOOL\SCHEMATICS_PARTS\MS_DISCRETE_Library.schlib; Mfr_name: YAGEO AMERICA; Mfr_part_number: RC0201JR-070RL; Mistral Part No: 110010070067-R; Package: 0201; Part_type: RESISTORS\FIXED; Project: PB_BUGBASE; RoHS: RoHS; SIGNAL_MODEL: RESISTOR_RES0201_0-5_22E_1%_22E_1%; Temperature: -55°C+125°C; Tolerance: 5%; Voltage: NA; Wattage: 1/20W; Weight: 0.17mg; Datasheet: Y:\MIS_DATABASE\DATASHEETS\RESISTORS\RCXXXXL-SER_MAR18.PDF
R466 R470 = RESISTOR: RES 0E 1/10W JUMPER 0402; Chkd/date: VASANTHA/061216; Crtd /date: NAVEED/201014; Custom_Duty: 15%; Customs_HS_Code: 85332119; Distributor_name: DIGIKEY; Distributor_part_number: P0.0JCT-ND; Footprint Path: Y:\MIS_DATABASE\Library\ALTIUM_TOOL\PCB_FOOTPRINTS\Altium_Footprint_Lib.PcbLib; Height: 0.40MM; IBISSP_MODLES: VALUE REPEATING 2 TIME; Library Path: Y:\MIS_DATABASE\Library\ALTIUM_TOOL\SCHEMATICS_PARTS\MS_DISCRETE_Library.schlib; Mfr_name: PANASONIC-ECG; Mfr_part_number: ERJ-2GE0R00X; Mistral Part No: 110018030052-R; Package: 0402; Part_type: RESISTORS\FIXED; Project: AEGIS POM; RoHS: RoHS; Temperature: -55°C+155°C; Tolerance: NA; Voltage: NA; Wattage: 1/10W; Weight: 0.8mg; Datasheet: Y:\MIS_DATABASE\DATASHEETS\RESISTORS\PAN-ERJSER_NOV17.PDF
U29 = SN74AVC2T244DQMR_X2SON8: IC 2-BIT UNDIRECTIONAL VOLTAGE-LEVEL TRANSLATOR X2SON8; Chkd/date: VASANTHA/060516; Crtd /date: VASANTHA/030316; Customs_HS_Code: 15%; Distributor_name: DIGIKEY; Distributor_part_number: 296-29674-1-ND; Height: 0.40MM; Mfr_name: TEXAS INSTRUMENTS; Mistral Part No: 141016030002-R; Package: X2SON8; Part_type: ICS\INTERFACE\LEVEL TRANSLATOR; Pb-Free: 85423100; Project: OCTASIC_3600; RoHS: RoHS; Temperature: -40°C+85°C; Tolerance: NA; Voltage: NA; Wattage: NA; Weight: NA; Datasheet: Y:\MIS_DATABASE\DATASHEETS\ICS\INTERFACE\SN74AVC2T244.PDF
U84 U85 = LCMXO2-256HC_VFQFN48: IC PLD MACHXO2 DEVICE VFQFN48; Chkd/date: PRADEEP/041024; Crtd /date: SHANKARI/041024; Custom_Duty: 15%; Customs_HS_Code: 85423100; Distributor_name: DIGIKEY; Distributor_part_number: LCMXO2-640HC-4SG48I-ND; Height: 1.00MM; Mfr_name: LATTICE; Mistral Part No: 141024100001-R; Package: VFQFN48; Part_type: ICS\DIGITAL\PLD; Project: AM62D EVM; RoHS: RoHS; Temperature: -40°C+100°C; Tolerance: NA; Voltage: NA; Wattage: NA; Weight: NA; Datasheet: Y:\MIS_DATABASE\DATASHEETS\ICS\DIGITAL\PLD\LCMXO2-640HC-4SG48I.PDF
R25 R420 R468 R472 R484 = RESISTOR: RES 0E 1/20W 5% 0201; Chkd/date: NAVEED/301214; Crtd /date: MUDDU/120710; Custom_Duty: 15%; Customs_HS_Code: 85332119; Distributor_name: DIGIKEY; Distributor_part_number: 311-0.0NCT-ND; Footprint Path: Y:\MIS_DATABASE\Library\ALTIUM_TOOL\PCB_FOOTPRINTS\Altium_Footprint_Lib.PcbLib; Height: 0.26MM; Library Path: Y:\MIS_DATABASE\Library\ALTIUM_TOOL\SCHEMATICS_PARTS\MS_DISCRETE_Library.schlib; Mfr_name: YAGEO AMERICA; Mfr_part_number: RC0201JR-070RL; Mistral Part No: 110010070067-R; Package: 0201; Part_type: RESISTORS\FIXED; Project: PB_BUGBASE; RoHS: RoHS; Temperature: -55°C+125°C; Tolerance: 5%; Voltage: NA; Wattage: 1/20W; Weight: 0.17mg; Datasheet: Y:\MIS_DATABASE\DATASHEETS\RESISTORS\RCXXXXL-SER_MAR18.PDF
U80 = SN74AVC4T245RSV_UQFN16: IC 2-BIT BUS TRANSCEIVER WITH CONFIGURABLE VOLTAGE TRANSLATION AND 3 STATE O/P UQFN16; Chkd/date: MANIRAJA/040520; Crtd /date: BAVISH/190411; Custom_Duty: 15%; Customs_HS_Code: 85423100; Distributor_name: DIGIKEY; Distributor_part_number: 296-24366-1-ND; Footprint Path: Y:\MIS_DATABASE\Library\ALTIUM_TOOL\PCB_FOOTPRINTS\Altium_Footprint_Lib.PcbLib; Height: 0.55MM; Library Path: Y:\MIS_DATABASE\Library\ALTIUM_TOOL\SCHEMATICS_PARTS\MS_BUSDRIVERTRANSCEIVER_Library.schlib; Mfr_name: TEXAS INSTRUMENTS; Mistral Part No: 141011040011-R; Package: UQFN16; Part_type: ICS\DIGITAL\BUSTRANSCEIVER; Project: HMC; RoHS: RoHS; Temperature: -40°C+85°C; Tolerance: NA; Voltage: NA; Wattage: NA; Weight: 41mg; Datasheet: Y:\MIS_DATABASE\DATASHEETS\ICS\DIGITAL\BUSTRANSCEIVER\SN74AVC4T245-SER.PDF
C20 C21 C35 C67 C341 C342 C353 C369 = CAP: CAP CERAMIC 1uF 10V 20% X6S 0201; Chkd/date: PRADEEP/130623; Crtd /date: PRADEEP/130623; Custom_Duty: 15%; Customs_HS_Code: 85322990; Distributor_name: DIGIKEY; Distributor_part_number: 490-GRT033C81A105ME13DTR-ND; Footprint Path: Y:\MIS_DATABASE\Library\ALTIUM_TOOL\PCB_FOOTPRINTS\Altium_Footprint_Lib.PcbLib; Height: 0.39MM; Library Path: Y:\MIS_DATABASE\Library\ALTIUM_TOOL\SCHEMATICS_PARTS\MS_DISCRETE_Library.schlib; Mfr_name: MURATA; Mfr_part_number: GRT033C81A105ME13D; Mistral Part No: 120022060020-R; Package: 0201; Part_type: CAPACITORS\CERAMIC; Project: AM62P_SK; RoHS: RoHS; Temperature: -55°C+105°C; Tolerance: 20%; Voltage: 10V; Wattage: NA; Weight: NA; Datasheet: Y:\MIS_DATABASE\DATASHEETS\CAPACITORS\GRT033C81A105ME13D.PDF
C26 C27 C345 C346 = CAP: CAP CERAMIC 47uF 10V 20% X5R 0805; Chkd/date: MANIRAJA/181018; Crtd /date: ALVY/181018; Custom_Duty: 15%; Customs_HS_Code: 85322990; Distributor_name: DIGIKEY; Distributor_part_number: 490-9961-1-ND; Footprint Path: Y:\MIS_DATABASE\Library\ALTIUM_TOOL\PCB_FOOTPRINTS\Altium_Footprint_Lib.PcbLib; Height: 1.45MM; Library Path: Y:\MIS_DATABASE\Library\ALTIUM_TOOL\SCHEMATICS_PARTS\MS_DISCRETE_Library.schlib; Mfr_name: MURATA; Mfr_part_number: GRM21BR61A476ME15L; Mistral Part No: 120014100011-R; Package: 0805; Part_type: CAPACITORS\CERAMIC; Project: RFID_MODULE-DESIGN; RoHS: RoHS; Temperature: -55°C+85°C; Tolerance: 20%; Voltage: 10V; Wattage: NA; Weight: 9.5mg; Datasheet: Y:\MIS_DATABASE\DATASHEETS\CAPACITORS\GRM21BR61A476ME15L.PDF
J4 = CON_AUDIOJACK6_STX-4235-3_3: CON AUDIO JACK DUAL 6POS 3.50MM FEMALE RT TH; Chkd/date: MANIRAJA/090818; Crtd /date: ALVY/080818; Custom_Duty: 24%; Customs_HS_Code: 85369090; Distributor_name: MOUSER; Distributor_part_number: 806-STX-4235-3/3-N; Footprint Path: Y:\MIS_DATABASE\Library\ALTIUM_TOOL\PCB_FOOTPRINTS\Altium_Footprint_Lib.PcbLib; Height: 26.00MM; Library Path: Y:\MIS_DATABASE\Library\ALTIUM_TOOL\SCHEMATICS_PARTS\MS_CONNECTOR_Library.schlib; Library Ref: CON_AUDIOJACK6_STX-4235-3/3; Mfr_name: KYCON; Mfr_part_number: STX-4235-3/3-N; Mistral Part No: 150018080005-R; Package: THRU-HOLE; Part_type: CONNECTOR\JACK; Project: TI_J7ES_EVM_FUSION2_SER_CAP; RoHS: RoHS; Temperature: -25°C+85°C; Tolerance: NA; Voltage: NA; Wattage: NA; Weight: NA; Datasheet: Y:\MIS_DATABASE\DATASHEETS\CONNECTORS\STX-4235-3-3-N.PDF
R28 = RESISTOR: RES 4.7K 1/20W 5% 0201; Chkd/date: MANIRAJA/200921; Crtd /date: ALVY/200921; Custom_Duty: 15%; Customs_HS_Code: 85332119; Distributor_name: DIGIKEY; Distributor_part_number: 311-4.7KNCT-ND; Footprint Path: Y:\MIS_DATABASE\Library\ALTIUM_TOOL\PCB_FOOTPRINTS\Altium_Footprint_Lib.PcbLib; Height: 0.26MM; Library Path: Y:\MIS_DATABASE\Library\ALTIUM_TOOL\SCHEMATICS_PARTS\MS_DISCRETE_Library.schlib; Mfr_name: YAGEO AMERICA; Mfr_part_number: RC0201JR-074K7L; Mistral Part No: 110021090007-R; Package: 0201; Part_type: RESISTORS\FIXED; Project: TI_AM62x SKEVM_BRD; RoHS: RoHS; Temperature: -55°C+125°C; Tolerance: 5%; Voltage: NA; Wattage: 1/20W; Weight: 0.17mg; Datasheet: Y:\MIS_DATABASE\DATASHEETS\RESISTORS\RCXXXXL-SER_MAR18.PDF
R35 = RESISTOR: RES 22K 1/16W 5% 0402; Chkd/date: MANIRAJA/310718; Crtd /date: BAVISH/021210; Custom_Duty: 15%; Customs_HS_Code: 85332119; Distributor_name: DIGIKEY; Distributor_part_number: 311-22KJRCT-ND; Footprint Path: Y:\MIS_DATABASE\Library\ALTIUM_TOOL\PCB_FOOTPRINTS\Altium_Footprint_Lib.PcbLib; Height: 0.40MM; Library Path: Y:\MIS_DATABASE\Library\ALTIUM_TOOL\SCHEMATICS_PARTS\MS_DISCRETE_Library.schlib; Mfr_name: YAGEO AMERICA; Mfr_part_number: RC0402JR-0722KL; Mistral Part No: 110010120021-R; Package: 0402; Part_type: RESISTORS\FIXED; Project: TE4; RoHS: RoHS; Temperature: -55°C+155°C; Tolerance: 5%; Voltage: NA; Wattage: 1/16W; Weight: 0.65mg; Datasheet: Y:\MIS_DATABASE\DATASHEETS\RESISTORS\RCXXXXL-SER_MAR18.PDF
TP11 TP14 TP19 TP20 TP23 TP110 TP111 TP114 = TESTPOINT: TESTPOINT CIR 30 SMD; Chkd/date: SHREESHAIL/171006; Crtd /date: MAZHAR/171006; Custom_Duty: NA; Customs_HS_Code: NA; Distributor_name: NA; Distributor_part_number: NA; Footprint Path: Y:\MIS_DATABASE\Library\ALTIUM_TOOL\PCB_FOOTPRINTS\Altium_Footprint_Lib.PcbLib; Height: NA; Library Path: Y:\MIS_DATABASE\Library\ALTIUM_TOOL\SCHEMATICS_PARTS\MS_DISCRETE_Library.schlib; MECHANICAL 3D STEP FILE: NA; Mfr_name: LOCAL; Mistral Part No: 130009030930; Package: SMD; Project: BT MODULE_CSRBC04; RoHS: NA; Temperature: NA; Tolerance: NA; Voltage: NA; Wattage: NA; Weight: NA; Datasheet: NA
U6 U76 = TAD5212IRGER_QFN24: IC HIGH-PERFORMANCE STEREO AUDIO WITH 115db DYNAMIC RANGE DAC QFN24; Chkd/date: PRADEEP/271223; Crtd /date: TAMILARASU/271223; Custom_Duty: 15%; Customs_HS_Code: 85423100; Distributor_name: NA; Distributor_part_number: NA; Footprint Path: Y:\MIS_DATABASE\Library\ALTIUM_TOOL\PCB_FOOTPRINTS\Altium_Footprint_Lib.PcbLib; Height: 1.00MM; Library Path: Y:\MIS_DATABASE\Library\ALTIUM_TOOL\SCHEMATICS_PARTS\MS_COMBINATIONAL_Library.schlib; Mfr_name: TEXAS INSTRUMENTS; Mistral Part No: 141023120021-R; Package: QFN24; Part_type: ICS\DIGITAL\DSP; Project: AM62D_EVM; RoHS: RoHS; Temperature: -40°C+125°C; Tolerance: NA; Voltage: NA; Wattage: NA; Weight: NA; Datasheet: Y:\MIS_DATABASE\DATASHEETS\ICS\DSP\TAD5212IRGER.PDF
U92 U113 U115 U119 U121 U123 = INA231_DSBGA12: IC HIGH OR LOW SIDE MEASUREMENT BI-DIR CURRENT AND POWER MONITOR WITH 1.8V I2C INTERFACE DSBGA12; Chkd/date: MANIRAJA/250821; Crtd /date: ALVY/250821; Custom_Duty: 15%; Customs_HS_Code: 85423100; Distributor_name: DIGIKEY; Distributor_part_number: 296-49645-1-ND; Footprint Path: Y:\MIS_DATABASE\Library\ALTIUM_TOOL\PCB_FOOTPRINTS\Altium_Footprint_Lib.PcbLib; Height: 0.40MM; Library Path: Y:\MIS_DATABASE\Library\ALTIUM_TOOL\SCHEMATICS_PARTS\MS_MISCPOWER_Library.schlib; Mfr_name: TEXAS INSTRUMENTS; Mistral Part No: 142021080022-R; Package: DSBGA12; Part_type: ICS\POWER\MANAGEMENT; Project: TI_AM62x SVB_BRD; RoHS: RoHS; Temperature: -40°C+125°C; Tolerance: NA; Voltage: NA; Wattage: NA; Weight: 200mg; Datasheet: Y:\MIS_DATABASE\DATASHEETS\ICS\POWER\INA231XXX.PDF

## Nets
AVDD_3V3_DAC: C30.1 C31.1 C349.1 C351.1 R28.2 R35.2 U6.23(AVDD) U76.23(AVDD) ; also on sheet 53
DGND: C20.1 C21.1 C30.2 C31.2 C35.2 C43.2 C46.2 C48.2 C51.2 C57.2 C62.2 C67.2 C73.2 C76.2 C145.2 C150.1 C151.1 C152.2 C153.2 C154.2 C155.2 C156.2 C158.2 C159.2 C163.2 C341.1 C342.1 C349.2 C351.2 C353.2 C355.2 C357.2 C359.2 C361.2 C364.2 C366.2 C369.2 C371.2 C373.2 C377.2 C392.1 C396.1 C397.2 C398.2 C399.2 C400.2 C401.2 C402.2 C403.2 C404.2 C405.2 C406.2 C407.2 C410.2 C411.2 C412.2 C413.2 J4.1A J4.1B J8.6 J11.6 R27.2 R30.2 R32.2 R143.2 R430.2 R458.2 R462.1 R467.2 U6.25(EP_PAD) U6.A1(VSS) U6.A2(VSS) U6.A3(VSS) U6.A4(VSS) U29.5(GND) U76.25(EP_PAD) U76.A1(VSS) U76.A2(VSS) U76.A3(VSS) U76.A4(VSS) U80.10(GND1) U80.11(GND2) U84.49(EP) U85.49(EP) U92.B3(A0) U92.C1(GND) U113.B3(A0) U113.C1(GND) U113.C3(A1) U115.C1(GND) U115.C3(A1) U119.C1(GND) U121.C1(GND) U123.C1(GND) ; also on sheet 1 2 3 4 5 6 7 8 9 10 12 13 14 16 17 18 31 32 33 34 35 36 37 38 39 40 41 42 43 44 45 46 47 48 49 50 51 52 53 54 55 56 57 58
DVDD1V8_ALERT: U123.A3(ALERT) ; also on sheet 18
DVDD3V3_ALERT: U92.A3(ALERT) ; also on sheet 18
VCC1V8_SYS: C73.1 C76.1 C151.2 C371.1 C373.1 C396.2 FL11.1 FL12.1 U6.6(IOVDD) U29.8(VCCB) U76.6(IOVDD) U80.2(VCCB) ; also on sheet 1 2 4 6 7 10 33 37 38 39 42 43 49 50 52 53 54 55 56 57 58
VCC_3V3_SYS: C145.1 C150.2 C152.1 C153.1 C154.1 C156.1 C159.1 C377.1 C392.2 C398.1 C399.1 C402.1 C403.1 C411.1 C413.1 J8.1 J11.1 R120.1 R142.1 R437.1 R455.2 R459.1 R460.1 R469.1 R471.1 R473.1 U29.1(VCCA) U80.3(VCCA) U84.1(VCC) U84.25(VCC) U84.39(VCCIO0) U84.46(VCCIO0) U85.1(VCC) U85.25(VCC) U85.39(VCCIO0) U85.46(VCCIO0) U92.B1(VS) U113.B1(VS) U115.B1(VS) U115.B3(A0) U119.B1(VS) U119.B3(A0) U121.B1(VS) U121.C3(A1) U123.B1(VS) U123.B3(A0) U123.C3(A1) ; also on sheet 1 2 3 6 10 14 17 18 31 33 37 38 40 41 42 45 46 48 49 50 51 52 53 54 55 56 57 58
VDD_CORE_ALERT: U113.A3(ALERT) ; also on sheet 18
VDD_CORE_N: U113.D1(BUS) U113.D2(IN-) ; also on sheet 18
VDD_CORE_P: U113.D3(IN+) ; also on sheet 18
VDD_LPDDR4_ALERT: U121.A3(ALERT) ; also on sheet 18
VDD_LPDDR4_N: U121.D1(BUS) U121.D2(IN-) ; also on sheet 18
VDD_LPDDR4_P: U121.D3(IN+) ; also on sheet 18
VDDA_1V8_ALERT: U119.A3(ALERT) ; also on sheet 18
VDDA_1V8_N: U119.D1(BUS) U119.D2(IN-) ; also on sheet 18
VDDA_1V8_P: U119.D3(IN+) ; also on sheet 18
VDDR_CORE_ALERT: U115.A3(ALERT) ; also on sheet 18
VDDR_CORE_N: U115.D1(BUS) U115.D2(IN-) ; also on sheet 18
VDDR_CORE_P: U115.D3(IN+) ; also on sheet 18
AUDIO_EXT_REFCLK0: R470.1 ; also on sheet 7
AUDIO_EXT_REFCLK1: R466.1 ; also on sheet 11
CP_GEMAC_CPTS0_HW1TSPUSH: U85.2(PL2A) ; also on sheet 7
CP_GEMAC_CPTS0_HW2TSPUSH: U85.8(PL3B) ; also on sheet 7
CPLD1_1V8_BANK_SUPPLY: C155.1 C158.1 C406.1 C407.1 C412.1 FL12.2 U84.6(VCCIO3) U84.13(VCCIO2) U84.22(VCCIO2) U84.30(VCCIO1)
CPLD1_CLOCKIN 1: U84.33(PR5B) ; also on sheet 50
CPLD1_CLOCKIN 2: U84.4(PL2C) ; also on sheet 50
CPLD1_DONE: R142.2 U84.37(PT9D) ; also on sheet 55
CPLD1_INTN: R460.2 U84.38(PT9C) ; also on sheet 55
CPLD1_JTAGENB: R458.1 U84.41(PT9A) ; also on sheet 55
CPLD1_PROGRAMN: R459.2 U84.40(PT9B) ; also on sheet 55
CPLD1_TCK: J8.2 U84.45(PT7A) ; also on sheet 55
CPLD1_TDI: J8.4 U84.47(PT6D) ; also on sheet 55
CPLD1_TDO: J8.5 U84.48(PT6C) ; also on sheet 55
CPLD1_TMS: J8.3 R437.2 U84.44(PT7B) ; also on sheet 55
CPLD2_1V8_BANK_SUPPLY: C163.1 C397.1 C400.1 C401.1 C404.1 C405.1 C410.1 FL11.2 U85.6(VCCIO3) U85.13(VCCIO2) U85.22(VCCIO2) U85.30(VCCIO1)
CPLD2_DONE: R473.2 U85.37(PT9D) ; also on sheet 55
CPLD2_INTN: R471.2 U85.38(PT9C) ; also on sheet 55
CPLD2_JTAGENB: R467.1 U85.41(PT9A) ; also on sheet 55
CPLD2_PROGRAMN: R469.2 U85.40(PT9B) ; also on sheet 55
CPLD2_TCK: J11.2 U85.45(PT7A) ; also on sheet 55
CPLD2_TDI: J11.4 U85.47(PT6D) ; also on sheet 55
CPLD2_TDO: J11.5 U85.48(PT6C) ; also on sheet 55
CPLD2_TMS: J11.3 R120.2 U85.44(PT7B) ; also on sheet 55
CPLD/EXP1_McASP0_ACLKR: R484.1 ; also on sheet 7 54
CPLD/EXP1_McASP0_AFSR: U85.36(PR3C) ; also on sheet 7 54
CPLD/EXP1_McASP0_AFSX: U85.34(PR5A) ; also on sheet 7 54
CPLD/EXP1_McASP0_AXR0: U85.32(PR5C) ; also on sheet 7 54
CPLD/EXP2_McASP2_ACLKX: U84.23(PB9A) ; also on sheet 6 11
CPLD/EXP2_McASP2_AFSR: U85.21(PB4D) ; also on sheet 6 11
CPLD/EXP2_McASP2_AFSX: U85.24(PB9B) ; also on sheet 6 11
CPLD/EXP2_McASP2_AXR0: U84.14(PB2A) ; also on sheet 6 11
CPLD/EXP2_McASP2_AXR1: U84.15(PB2B) ; also on sheet 6 11
CPLD/EXP2_McASP2_AXR3: U84.16(PB2C) ; also on sheet 6 11
CPLD/EXP2_McASP2_AXR4: U84.17(PB2D) ; also on sheet 6 11
CPLD_CDCE_CLKOUT_1: U84.32(PR5C) ; also on sheet 50
CPLD_CDCE_CLKOUT_2: U84.34(PR5A) ; also on sheet 50
CPLD_CPSW_RGMII1_BCLK: U29.3(A2) ; also on sheet 40
CPLD_CPSW_RGMII1_BCLK_1V8: U29.6(B2) U84.35(PR3D)
CPLD_CPSW_RGMII1_COL: U80.7(1A2) ; also on sheet 40
CPLD_CPSW_RGMII1_COL_1V8: U80.14(1B2) U85.15(PB2B)
CPLD_CPSW_RGMII1_CRS: U80.6(1A1) ; also on sheet 40
CPLD_CPSW_RGMII1_CRS_1V8: U80.15(1B1) U85.14(PB2A)
CPLD_CPSW_RGMII2_BCLK: U29.2(A1) ; also on sheet 41
CPLD_CPSW_RGMII2_BCLK_1V8: U29.7(B1) U84.36(PR3C)
CPLD_CPSW_RGMII2_COL: U80.9(2A2) ; also on sheet 41
CPLD_CPSW_RGMII2_COL_1V8: U80.12(2B2) U85.17(PB2D)
CPLD_CPSW_RGMII2_CRS: U80.8(2A1) ; also on sheet 41
CPLD_CPSW_RGMII2_CRS_1V8: U80.13(2B1) U85.16(PB2C)
CPLD_ECAP0_APWM_OUT: U85.11(PL5A) ; also on sheet 7
CPLD_ECAP1_APWM_OUT: U85.12(PL5B) ; also on sheet 7
CPLD_ECAP2_APWM_OUT: U85.7(PL3A) ; also on sheet 7
CPLD_McASP1_AFSR: U85.27(PR6C) ; also on sheet 37 54
CPLD_McASP1_AFSX: U85.26(PR6D) ; also on sheet 37 54
CPLD_OBSCLK0: U84.12(PL5B) ; also on sheet 11
CPLD_OBSCLK1: U84.29(PR6A) ; also on sheet 7
CPLD_UART0_RXD: U85.18(PB4A) ; also on sheet 4
CPLD_UART0_TXD: U85.19(PB4B) ; also on sheet 4
DIX4192_McASP0_ACLKR: U85.28(PR6B) ; also on sheet 49
DIX4192_McASP0_AFSR: U85.35(PR3D) ; also on sheet 49
DIX4192_McASP0_AFSX: U85.33(PR5B) ; also on sheet 49
DIX4192_McASP0_AXR0: U85.31(PR5D) ; also on sheet 49
DIX_MCLK: R463.2 ; also on sheet 49
DIX_RVD_CLK: U84.9(PL3C) ; also on sheet 49
EXP1_CLK_IN: U84.3(PL2B) ; also on sheet 54
EXP1_CLK_OUT: U84.2(PL2A) ; also on sheet 54
EXP1_TIMESTAMP0_IN: U85.4(PL2C) ; also on sheet 54
EXP1_TIMESTAMP1_IN: U85.5(PL2D) ; also on sheet 54
EXP2_CLK_IN: U84.8(PL3B) ; also on sheet 6
EXP2_CLK_OUT: U84.7(PL3A) ; also on sheet 6
EXP2_TIMESTAMP0_IN: U85.9(PL3C) ; also on sheet 6
EXP2_TIMESTAMP1_IN: U85.10(PL3D) ; also on sheet 6
EXT_REFCLK1: U84.28(PR6B) ; also on sheet 7
PCM6240_BUF_EN: U84.10(PL3D) ; also on sheet 16
PCM6240_McASP2_AFSR: R468.2 ; also on sheet 5 56
RESETSTATZ_1V8: U84.11(PL5A) U85.3(PL2B) ; also on sheet 10 50
SoC_DVDD1V8_N: U123.D1(BUS) U123.D2(IN-) ; also on sheet 18
SoC_DVDD1V8_P: U123.D3(IN+) ; also on sheet 18
SoC_DVDD3V3_N: U92.D1(BUS) U92.D2(IN-) ; also on sheet 18
SoC_DVDD3V3_P: U92.D3(IN+) ; also on sheet 18
SoC_I2C0_SCL: U84.43(PT8C) U85.43(PT8C) ; also on sheet 1 3 17 40 41 50 55
SoC_I2C0_SCL_1V8: U6.7(SCL) U76.7(SCL) ; also on sheet 1 5 7 49 50 53 56
SoC_I2C0_SCL_R1: U92.A1(SCL) U92.C3(A1) U113.A1(SCL) U115.A1(SCL) U119.A1(SCL) U119.C3(A1) U121.A1(SCL) U121.B3(A0) U123.A1(SCL) ; also on sheet 17 18 31
SoC_I2C0_SDA: U84.42(PT8D) U85.42(PT8D) ; also on sheet 1 3 17 40 41 50 55
SoC_I2C0_SDA_1V8: U6.8(SDA) U76.8(SDA) ; also on sheet 1 5 7 49 50 53 56
SoC_I2C0_SDA_R1: U92.A2(SDA) U113.A2(SDA) U115.A2(SDA) U119.A2(SDA) U121.A2(SDA) U123.A2(SDA) ; also on sheet 17 18 31
TAD3_ADDR3: R30.1 R35.1 U6.13(ADDR)
TAD3_DREG_OUT: C43.1 C46.1 U6.1(DREG)
TAD3_GPI3: R32.1 U6.12(GPI1)
TAD3_MICBIAS: C67.1 U6.14(MICBIAS)
TAD3_VREF: C35.1 U6.24(VREF)
TAD4_ADDR4: R27.1 R28.1 U76.13(ADDR)
TAD4_DREG_OUT: C355.1 C357.1 U76.1(DREG)
TAD4_GPI4: R430.1 U76.12(GPI1)
TAD4_MICBIAS: C369.1 U76.14(MICBIAS)
TAD4_VREF: C353.1 U76.24(VREF)
TAD5212_1_DIN: R479.1 ; also on sheet 53
TAD5212_1_DIN_R: R479.2 U84.18(PB4A)
TAD5212_2_DIN: R478.1 ; also on sheet 53
TAD5212_2_DIN_R: R478.2 U84.19(PB4B)
TAD5212_3_DIN: R477.1 U6.5(DIN)
TAD5212_3_DIN_R: R477.2 U84.20(PB4C)
TAD5212_4_DIN: R475.1 U76.5(DIN)
TAD5212_4_DIN_R: R475.2 U84.21(PB4D)
TAD5212_McASP2_ACLKX: R474.1 U6.2(BCLK) U76.2(BCLK) ; also on sheet 53
TAD5212_McASP2_AFSX: R472.2 U6.3(FSYNC) U76.3(FSYNC) ; also on sheet 53
N24851304: R420.1 U76.4(DOUT)
N24851306: R420.2 TP14.1(TP)
N24851312: C346.1 J4.5B
N24851314: C345.1 J4.2B
N24851316: C345.2 U76.21(OUT2P)
N24851320: C342.2 U76.19(OUT1M)
N24851322: C341.2 U76.22(OUT2M)
N24851338: C346.2 U76.20(OUT1P)
N24851340: TP111.1(TP) U76.11(GPO1)
N24851385: C366.1 U76.15(IN1P)
N24851391: C364.1 U76.16(IN1M)
N24851397: C361.1 U76.17(IN2P)
N24851403: C359.1 U76.18(IN2M)
N24851421: TP110.1(TP) U76.9(GPIO1)
N24851423: TP114.1(TP) U76.10(GPIO2)
N24851452: R25.1 U6.4(DOUT)
N24851454: R25.2 TP11.1(TP)
N24851456: C27.1 J4.5A
N24851458: C26.1 J4.2A
N24851460: C26.2 U6.21(OUT2P)
N24851462: C21.2 U6.19(OUT1M)
N24851464: C20.2 U6.22(OUT2M)
N24851486: C27.2 U6.20(OUT1P)
N24851488: TP20.1(TP) U6.11(GPO1)
N24851535: C62.1 U6.15(IN1P)
N24851541: C57.1 U6.16(IN1M)
N24851547: C51.1 U6.17(IN2P)
N24851553: C48.1 U6.18(IN2M)
N24851571: TP19.1(TP) U6.9(GPIO1)
N24851573: TP23.1(TP) U6.10(GPIO2)
N26451841: R472.1 U85.23(PB9A)
N26451883: R468.1 U85.20(PB4C)
N26455193: R455.1 U80.4(1DIR) U80.5(2DIR)
N26455313: R462.2 U80.1(~{1OE}) U80.16(~{2OE})
N26461930: R143.1 U29.4(~{OE})
N26517285: R463.1 U84.31(PR5D)
N26567066: R474.2 U84.24(PB9B)
N27056893: R484.2 U85.29(PR6A)
N27417083: R470.2 U84.26(PR6D)
N27417117: R466.2 U84.27(PR6C)

Not connected (* = marked no-connect by the designer): U84 5(PL2D)*; U92 B2(NC1)* C2(NC2)*; U113 B2(NC1)* C2(NC2)*; U115 B2(NC1)* C2(NC2)*; U119 B2(NC1)* C2(NC2)*; U121 B2(NC1)* C2(NC2)*; U123 B2(NC1)* C2(NC2)*

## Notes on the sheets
sheet 19
- CURRENT MONITORING DEVICES - 1
- VDD_CORE
- SoC_DVDD1V8
- I2C ADDRESS: 0x40
- I2C ADDRESS: 0x45
- VDDA_1V8
- VDDR_CORE
- I2C ADDRESS: 0x4D
- I2C ADDRESS: 0x41
- VDD_LPDDR4
- SoC_DVDD3V3
- I2C ADDRESS: 0x47
- I2C ADDRESS: 0x4C
- Note: The design supports current/voltage measurements
  using either INA228 or INA231.
  (Implemented via stacked PCB footprint).
- INA I2C SLAVE ADDRESS
- SLAVE
  ADDRESS
  (IN HEX)
- POWER SOURCE
- SUPPLY NET
- VCC_CORE
- VDD_CORE
- 40
- VCC_0V85
- VDDR_CORE
- 41
- VCC_3V3_SYS
- SoC_DVDD3V3
- 4C
- VCC_1V8
- SoC_DVDD1V8
- 45
- VDDA1V8
- VDDA_1V8
- 4D
- VCC1V1
- VDD_LPDDR4
- 47
- PROC180E2_SCH
sheet 20
- CPLD 2
- CPLD2 LEVEL TRANSLATOR
- PROGRAMMING HEADER
- Silk Screen "CPLD JTAG"
sheet 21
- AUDIO - STEREO LINEOUT - 2
- DAC Supply & Decaps
- I2C ADDRESS: 0x52
- CAD Note: Place these decaps near the DVDD supply pin of DAC's
- Device Straps
- I2C ADDRESS: 0x53
sheet 22
- CPLD 1
- CPLD 1 LEVEL TRANSLATOR
- PROGRAMMING HEADER
- Silk Screen "CPLD JTAG"
sheet 23
- AM62D EVM
- TABLE OF CONTENTS
- PAGE
- CONTENTS
- PAGE
- CONTENTS
- BOARD REVISION
- E2
- 01
- TABLE OF CONTENTS
- 41
- AUDIO -  LINE OUT 2
- SCHEMATIC VERSION
- 0.1
- 02
- REVISION HISTORY
- 42
- AUDIO - MICROPHONE/LINEIN 1
- 03
- LINK TO DESIGN COLLATERALS AND FAQs
- 43
- AUDIO - MICROPHONE/LINEIN 2
- 04
- BLOCK DIAGRAM AM62D EVM
- 44
- PCM6240 BUFFERS
- 05
- BLOCK DIAGRAM XDS110 DEBUGGER
- 45
- AUDIO -  EXPANSION 1
- 06
- POWER ARCHITECTURE BLOCK DIAGRAM
- 46
- AUDIO -  EXPANSION 2
- 07
- POWER SEQUENCE
- 47
- MCAN INTERFACE
- 48
- BOOTMODE BUFFERS AND IO EXPANDERS
- 08
- I2C TREE
- 09
- GPIO MAPPING TABLE
- 49
- IO EXPANDER & USER TEST LED
- 50
- BOARD ID EEPROM & TEMPERATURE SENSORS
- 10
- USB TYPE-C POWER
- 11
- USB TYPE-C POWER CONNECTOR
- 51
- CURRENT MONITORING DEVICES - 1
- 52
- CURRENT MONITORING DEVICES - 2 (ALTERNATIVE)
- 12
- PRE-REGULATOR POWER SUPPLY
- 13
- SOC POWER SUPPLY PMIC - 1
- 53
- FT4232 UART TO USB BRIDGE
- 54
- 14
- SOC POWER SUPPLY PMIC - 2
- FT4232 UART BUFFERS
- 15
- SOC POWER SUPPLIES - LDOs
- 55
- XDS110 DEBUGGER
- 16
- SOC POWER SUPPLIES, SUPPLY RAILS AND SOC GROUND VSS
- 56
- XDS110 JTAG BUFFER
- 17
- SOC POWER SUPPLIES - DECAPS 1
- 57
- XDS110 TEST AUTOMATION BUFFERS
- 18
- SOC POWER SUPPLIES - DECAPS 2
- 58
- JTAG 20 PIN cTI CONNECTOR
- SOC WKUP /MCU DOMAIN & OSCILLATOR AND CLOCK BUFFER
- 19
- 59
- ASSEMBLY NOTES AND MOUNTING HARDWARE
- 20
- CPLD CLOCK GENERATION
- SOC RESET -1
- 21
- 22
- SOC RESET -2
- Note:
  Verify the DNI components configuration with respect to
  the EVM schematics (Use PDF) after  completion of design
  before board assembly
- 23
- BOOT MODE SWITCHES
- 24
- SoC DDR AND LPDDR4 DEVICE INTERFACE
- 25
- SOC OSPI INTERFACE AND OSPI DEVICE INTERFACE
- 26
- SOC MMC[0:2] INTERFACE AND eMMC FLASH + RESET
- 27
- SD CARD - LOAD SWITCH, LOAD SWITCH RESET LOGIC
- 28
- SOC PERIPHERALS 1 - GPMC AND CPSW3G ETHERNET INTERFACE
- 29
- SOC PERIPHERALS 2 - USB AND CSI INTERFACE(UNUSED)
- 30
- SOC PERIPHERALS 3 - McASP, UART, SPI, I2C, MCAN, JTAG
- 31
- CPSW3G RGMII_1 ETHERNET CONNECTOR 1
- CPSW3G RGMII_2 ETHERNET CONNECTOR 2
- 32
- 33
- POWER SUPPLY (CORE) FOR ETHERNET CONNECTOR
- USB0 TYPE-C DRP
- 34
- 35
- USB1 TYPE-A CONNECTOR, VBUS DIVIDER & POWER SWITCH
- 36
- CPLD 1
- 37
- CPLD 2
- 38
- AUDIO -  DIGITAL IN & OUT, OPTICAL IN - 1
- 39
- AUDIO -  DIGITAL IN & OUT, OPTICAL IN - 2
- 40
- AUDIO -  LINE OUT 1
sheet 24
- REVISION HISTORY
- VER #
- DATE
- DESCRIPTION OF CHANGES
- AUTHOR
- REVIEWED  BY
- APPROVED  BY
- 0.1
- 14 NOV 2023
- Initial Draft
- Mistral Design Team
- 0.2
- 21 NOV 2023
- Migrated to Burton PMIC and updated PDN as per AM62D EVM requirement
- Mistral Design Team
- Nishant
- 0.3
- 27 NOV 2023
- Implemented Audio section as per AM62D EVM requirements
- Mistral Design Team
- Nishant
- 0.4
- 14 DEC 2023
- Internally reviewed and shared with TI for review
- Mistral Design Team
- Nishant
- Ajit MB
- 1. Implemented Audio Expansions & CPLD
  2. Replaced Audio Lineout devices with TAD5212
- 0.5
- 27 DEC 2023
- Mistral Design Team
- 0.6
- 29 DEC 2023
- Implemented review comments from TI
- Mistral Design Team
- Nishant
- Ajit MB
- 0.7
- 07 FEB 2024
- Updated AEC, McASP Muxing, CPLD, Current Monitoring Sections
- Mistral Design Team
- E1
- 0.8
- 21 FEB 2024
- Updated Ethernet Expansion, FET Bus Switch & Voltage level translators
- Mistral Design Team
- 03 MAR 2024
- Updated Switch for fet selection and implemented TI comments
- 0.9
- Mistral Design Team
- 0.10
- 22 MAR 2024
- Updated Audio section,CPLD1 and CPLD2 connections removed FET switches as per TI comments.
- Mistral Design Team
- 0.11
- 28 MAR 2024
- Implemented review comments from TI
- Mistral Design Team
- 0.12
- 04 APRIL 2024
- Implemented review comments from TI
- Mistral Design Team
- 0.13
- 17 APRIL 2024
- Implemented modular approach
- Mistral Design Team
- 1.0
- 10 MAY 2024
- Baselined
- Mistral Design Team
- 1. ECR/ECN Implemented from E1 Revision
- 2. Removed RGMII1_INH and RGMII2_INH connection to "PMIC_EN" section
- 3. TXS0104EPWR(U32) IC replaced with TXB0104PWR
- 4. Implemented SYNC1_OUT resistor option as per the TI comments
- 5. Implemented PORT1 and PORT 2_15W_EN Status indication LED logic
- E2
- 0.1
- 06 SEP 2024
- Shrinivas
- Pandiya Rajan
- 6. Connected CPLD JTAG pins to GPIO expander
- Ajit MB
- 7. Changed 0.1uF decoupling caps on PMIC output to 0603 package
- 8. Changed package size for ADC input caps
- 9. DAC MCP47CVB02 U22 is changed to DAC53002 as per TI comments
- 10. Bootmode signals net names is been changed and default function of Bootmode is implemented
       as per the TI comments.
- 11. LCMXO2-256HC-4SG48I (U84 &U85 ) IC replaced with LCMXO2-640HC-4SG48I
- Shrinivas
- 1.0
- 20 SEP 2024
- Baselined
- Pandiya Rajan
- Ajit MB
sheet 25
- BLOCK DIAGRAM AM62D EVM
sheet 26
- BLOCK DIAGRAM_XDS110
sheet 27
- POWER ARCHITECTURE BLOCK DIAGRAM
sheet 28
- POWER  UP SEQUENCE
- POWER DOWN SEQUENCE
sheet 29
- I2C TREE
sheet 30
- GPIO MAPPING TABLE
